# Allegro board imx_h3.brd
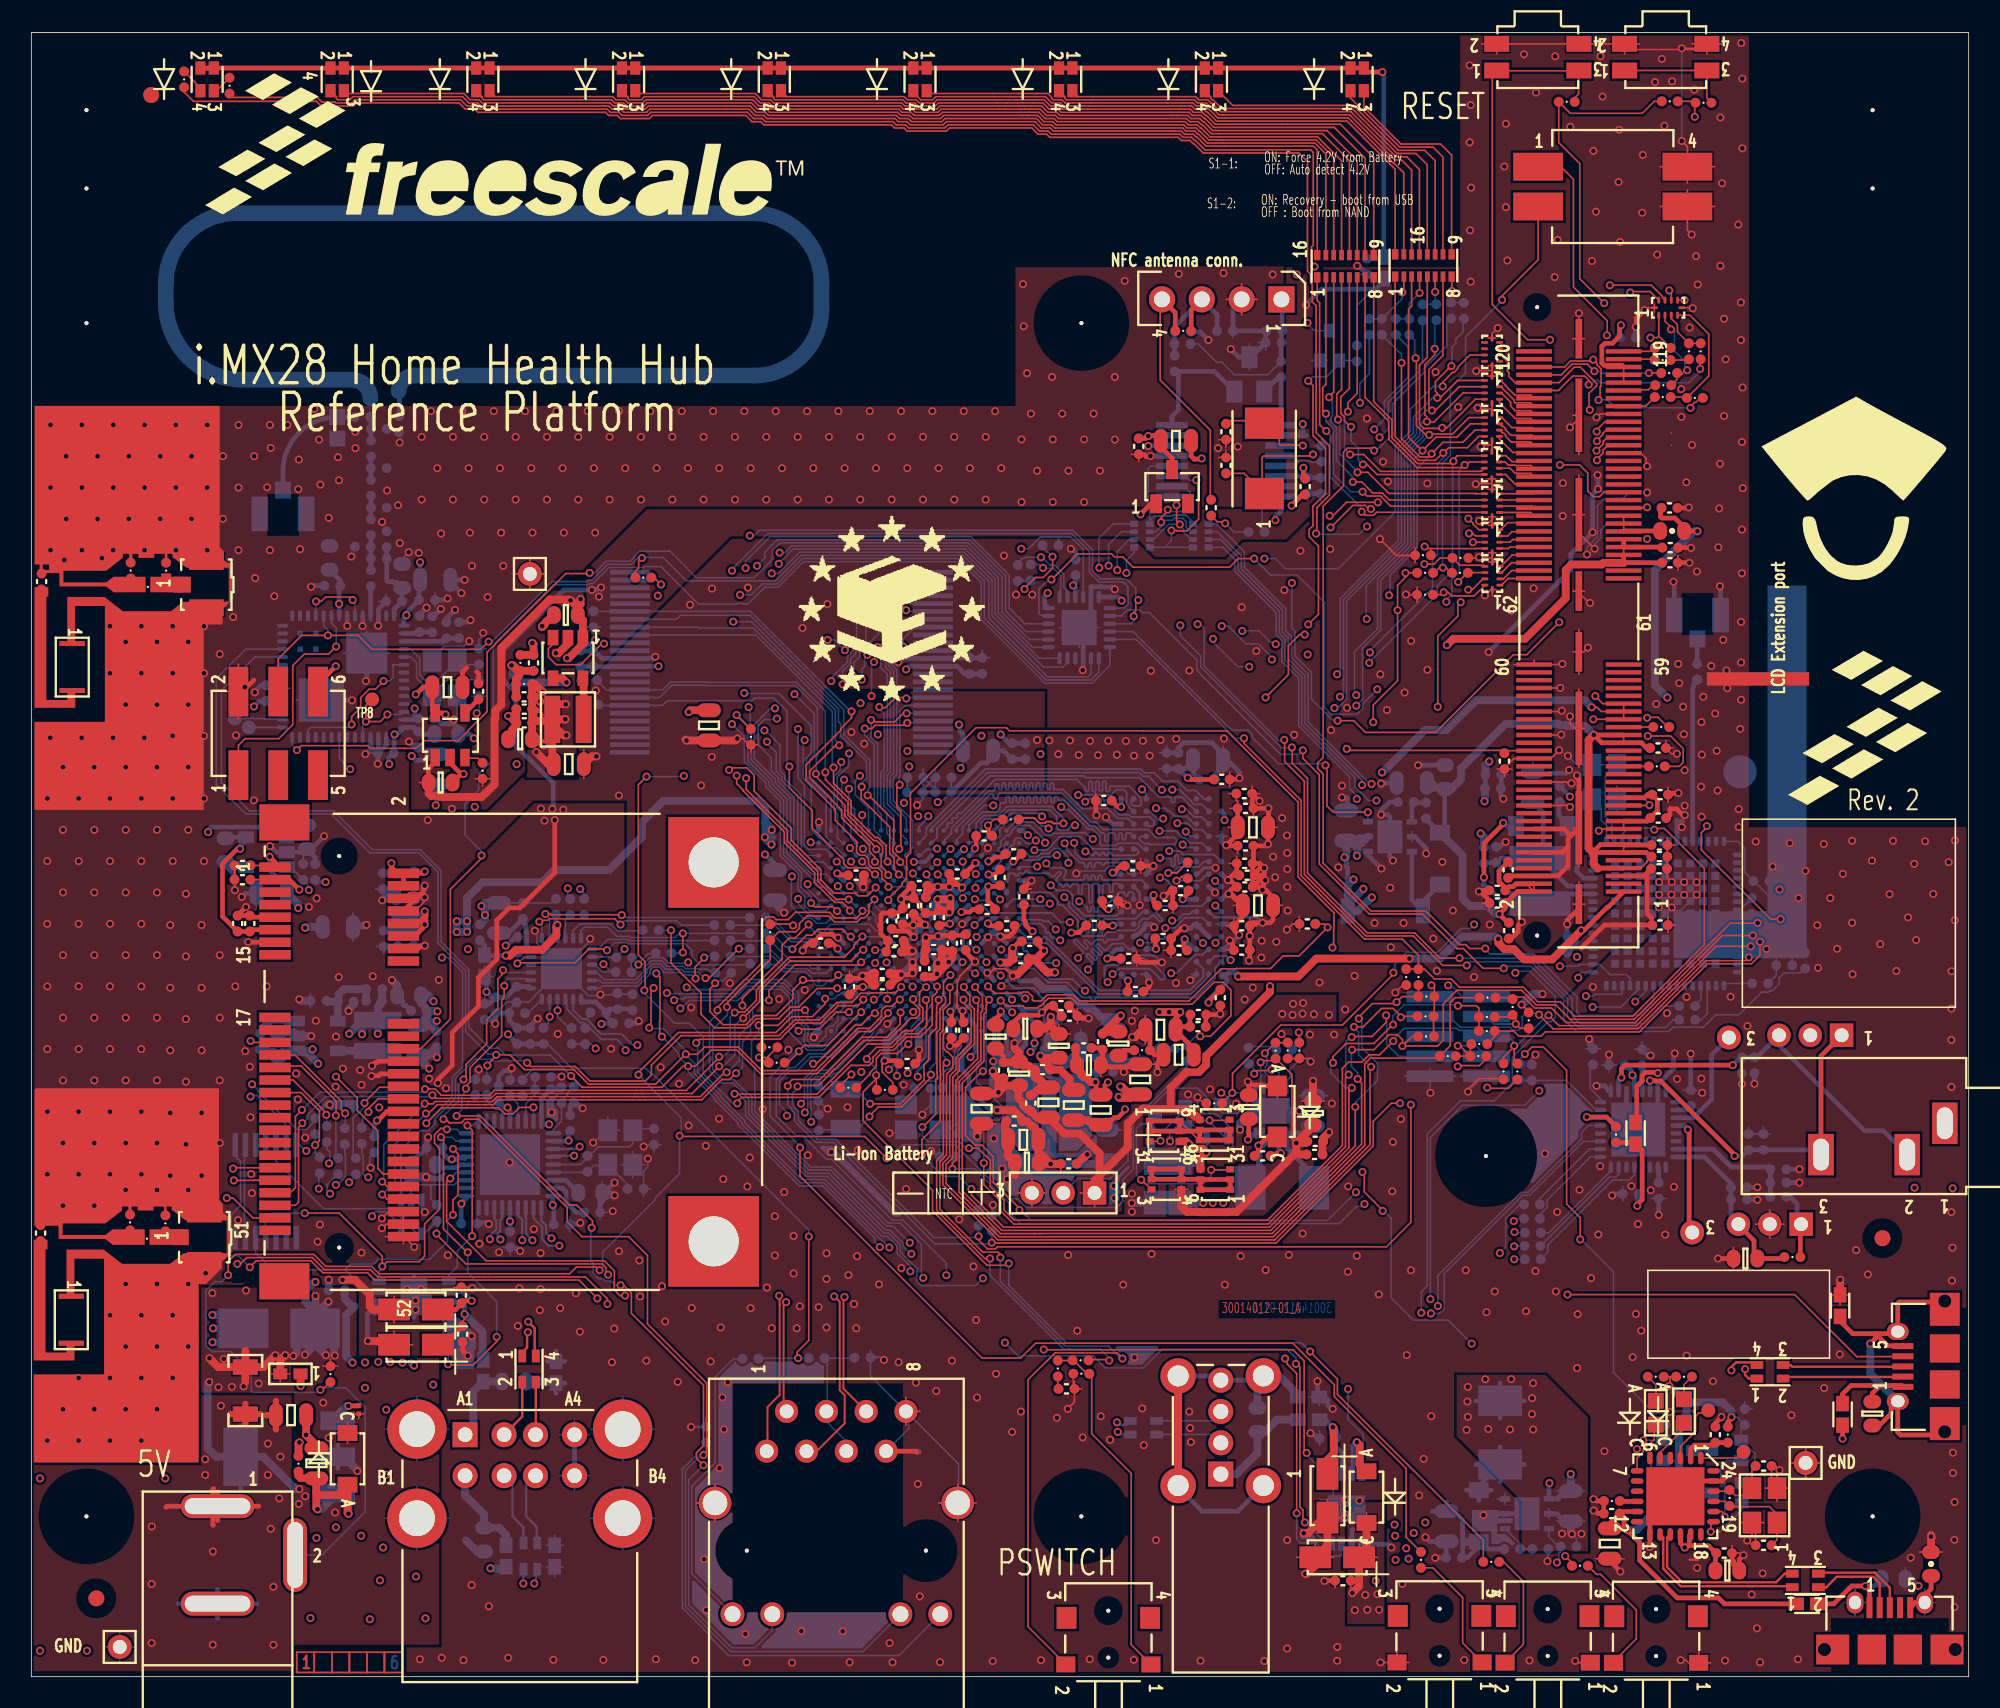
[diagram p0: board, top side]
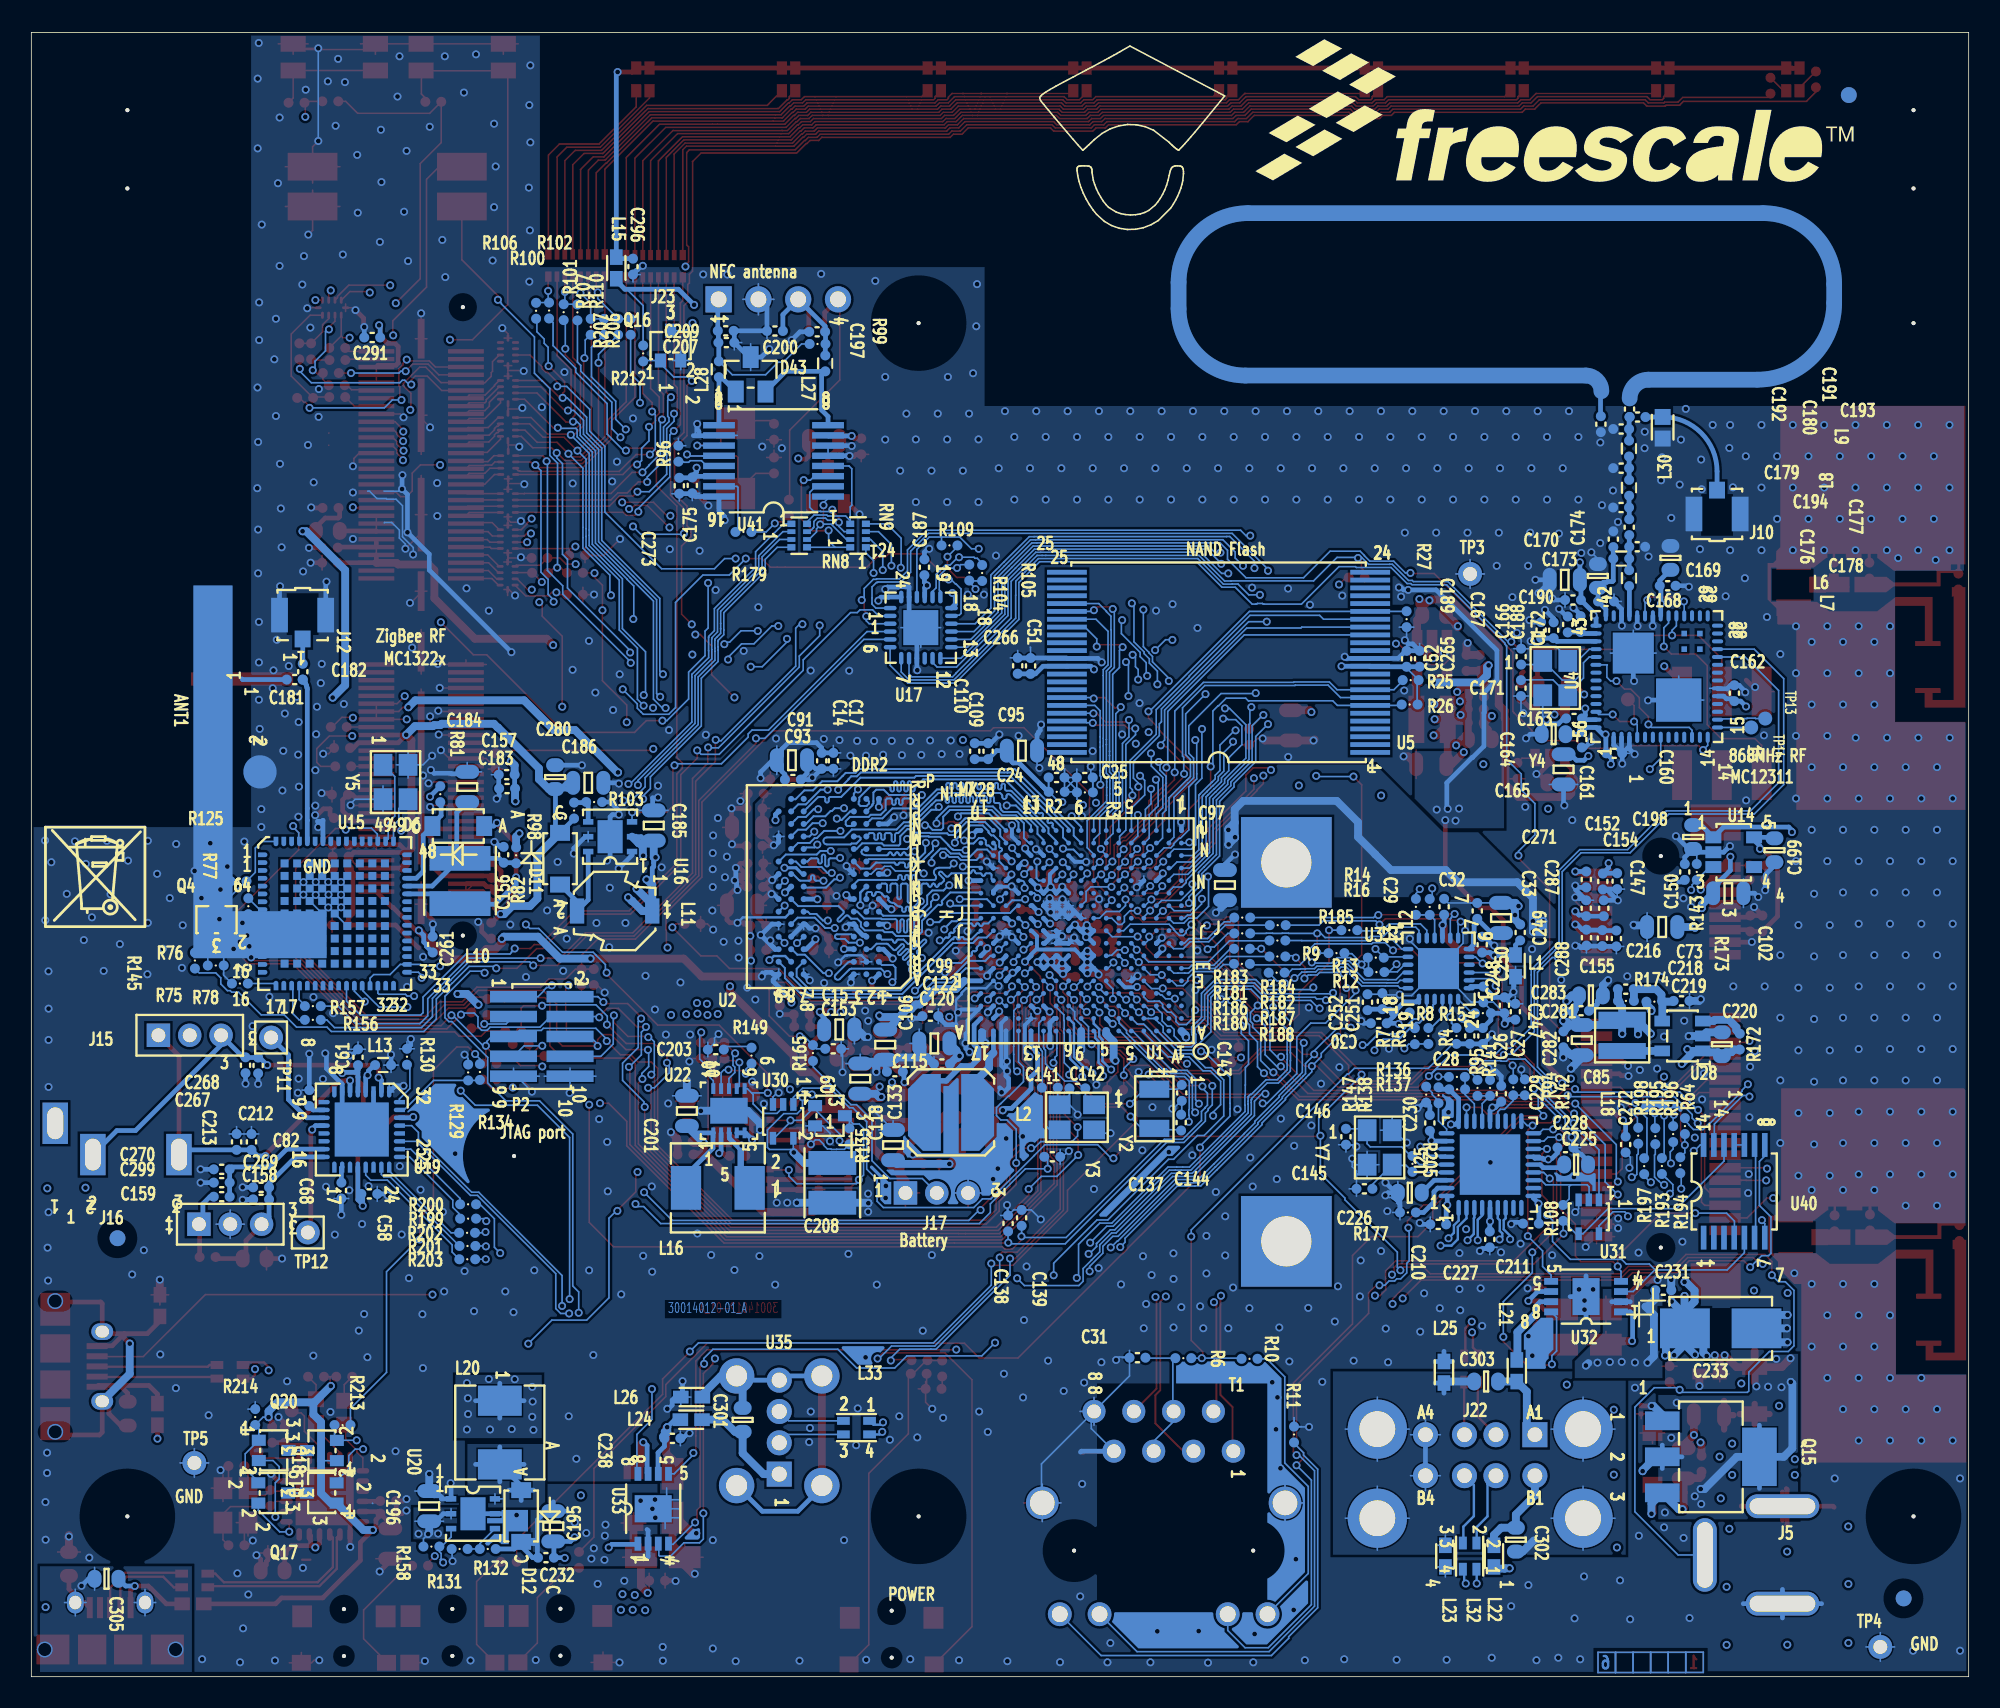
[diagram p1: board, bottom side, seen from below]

Outline 123.65 x 105 mm; copper layers: TOP, GND1, INT1, PWR, GND2, BOTTOM. Coordinates in mm from the lower left corner of the outline.
Outline path: 0,105 0,0 123.65,0 123.65,105 0,105

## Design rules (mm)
net group DDR2_CLK_DP: nets DDR2_CLK DDR2_CLK_B
net group DDR2_DQS0_DP: nets DDR2_DQS0 DDR2_DQS0_B
net group DDR2_DQS1_DP: nets DDR2_DQS1 DDR2_DQS1_B
net group ETH_RX_DIFF_PAIR: nets ETH_RXN ETH_RXP
net group ETH_TX_DIFF_PAIR: nets ETH_TXN ETH_TXP
net group USB0_DIFF_PAIR: nets USB0_DM USB0_DP
net group USB1_DIFF_PAIR: nets USB1_DM USB1_DP
net group USB_BOT_DIFF_PAIR: nets USB_BOT_DM USB_BOT_DP
net group USB_DEBUG_DIFF_PAIR: nets USB_DEBUG_DM USB_DEBUG_DP
net group USB_MODEM_DIFF_PAIR: nets USB_MODEM_DM USB_MODEM_DP
net group USB_TOP_DIFF_PAIR: nets USB_TOP_DM USB_TOP_DP
nets with their own width: min track width 0.12; nets DDR2_A0 DDR2_A1 DDR2_A2 DDR2_A3 DDR2_A4 DDR2_A5 DDR2_A6 DDR2_A7 DDR2_A8 DDR2_A9 DDR2_A10 DDR2_A11 DDR2_A12 DDR2_A13 DDR2_A14 DDR2_BA0 DDR2_BA1 DDR2_BA2 DDR2_CAS_B DDR2_CKE DDR2_CS_B DDR2_D00 DDR2_D01 DDR2_D02 DDR2_D03 DDR2_D04 DDR2_D05 DDR2_D06 DDR2_D07 DDR2_D08 DDR2_D09 DDR2_D10 DDR2_D11 DDR2_D12 DDR2_D13 DDR2_D14 DDR2_D15 DDR2_DQM0 DDR2_DQM1 DDR2_ODT0 DDR2_OPEN DDR2_RAS_B DDR2_WE_B

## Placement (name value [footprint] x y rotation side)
ANT1  F_Antenna  [F_ANTENNA_DIG528-2]  110.2 63.72 270 top
C1  10UF  [CC0805_OV]  78.29 49.25 0 top
C2  0.1UF  [CC0402_25]  77.26 47.95 0 top
C3  0.1UF  [CC0402_25]  77.26 46.4 0 top
C4  0.1UF  [CC0402_25]  75.89 43.36 270 top
C5  0.1UF  [CC0402_25]  74.45 41.5 0 top
C6  0.1UF  [CC0402_25]  68.45 55.95 180 top
C7  0.22uF  [CC0402_25]  70.47 43.75 0 top
C8  0.22uF  [CC0402_25]  77.5 55.45 0 top
C9  0.1UF  [CC0402_25]  77.5 53.06 0 top
C10  0.1UF  [CC0402_25]  68.85 49.53 0 top
C11  0.1UF  [CC0402_25]  77.45 50.43 0 top
C12  0.1UF  [CC0402_25]  77.6 51.18 0 top
C13  0.1UF  [CC0402_25]  70.03 45.86 0 top
C14  0.22uF  [CC0402_25]  73.2 58.49 90 bottom
C15  10UF  [CC0805_OV]  72.09 41.33 180 bottom
C16  0.01uF  [CC0402_25]  77.44 51.94 0 top
C17  0.01uF  [CC0402_25]  72.46 58.49 90 bottom
C18  0.1UF  [CC0402_25]  73.35 50.2 180 top
C19  0.1UF  [CC0402_25]  72.24 47.14 0 top
C20  0.1UF  [CC0402_25]  67.84 47.97 180 top
C21  0.1UF  [CC0402_25]  72.37 49.25 0 top
C22  0.1UF  [CC0402_25]  70.29 51.78 0 top
C23  0.22uF  [CC0402_25]  73.25 46.38 180 top
C24  0.1UF  [CC0402_25]  58.21 57.42 180 bottom
C25  0.1UF  [CC0402_25]  56.41 57.42 180 bottom
C26  0.01uF  [CC0402_25]  31.01 40.91 90 bottom
C27  0.01uF  [CC0402_25]  29.63 42.88 270 bottom
C28  0.1UF  [CC0402_25]  31.84 40.92 90 bottom
C29  0.01uF  [CC0402_25]  33.48 49.16 90 bottom
C30  0.01uF  [CC0402_25]  37.65 41.72 0 bottom
C31  0.022UF  [CC0402_25]  53.05 20.37 0 bottom
C32  0.1UF  [CC0402_25]  31.37 48.9 90 bottom
C33  10UF  [CC0805_OV]  29.84 48.45 90 bottom
C34  0.1UF  [CC0402_25]  107.48 15.46 90 top
C35  0.1UF  [CC0402_25]  100.87 10.41 180 top
C51  0.1UF  [CC0402_25]  59.88 64.54 90 bottom
C52  0.1UF  [CC0402_25]  35.88 65 90 bottom
C57  0.22uF  [CC0402_25]  57.59 46.43 180 top
C58  0.1UF  [CC0402_25]  102.08 30.83 180 bottom
C59  0.22uF  [CC0402_25]  57.02 45.21 90 top
C60  0.1UF  [CC0402_25]  57.95 48.47 90 top
C61  0.1UF  [CC0402_25]  102.8 39.56 90 bottom
C62  0.1UF  [CC0402_25]  58.78 46.84 90 top
C63  10UF  [CC0805_OV]  68.25 36.19 270 top
C64  0.22uF  [CC0402_25]  54.92 48.26 90 top
C65  0.1UF  [CC0402_25]  55.61 48.56 90 top
C66  0.1UF  [CC0402_25]  52.22 44.07 90 top
C67  0.1UF  [CC0402_25]  50.38 46.84 180 top
C68  0.1UF  [CC0402_25]  103.86 31.04 270 bottom
C69  0.1UF  [CC0402_25]  65.72 42.85 0 top
C70  0.1UF  [CC0402_25]  55.89 39.15 0 top
C71  0.1UF  [CC0402_25]  52.64 51.18 0 top
C72  0.1UF  [CC0402_25]  56.3 49.22 90 top
C73  10UF  [CC0805_OV]  19.56 47.88 0 bottom
C74  0.1UF  [CC0402_25]  54.31 44.91 180 top
C75  0.1UF  [CC0402_25]  54.31 44.19 180 top
C76  0.1UF  [CC0402_25]  55.06 46.29 180 top
C77  0.1UF  [CC0402_25]  55.17 47 180 top
C78  10UF  [CC0805_OV]  77.97 54.24 0 top
C79  0.1UF  [CC0402_25]  63.15 45.85 0 top
C80  0.1UF  [CC0402_25]  61 49 0 top
C81  0.22uF  [CC0402_25]  56.67 50.51 180 top
C82  0.1UF  [CC0402_25]  105.91 36.95 90 bottom
C83  0.1UF  [CC0402_25]  59.64 46.91 90 top
C84  0.22uF  [CC0402_25]  59.09 51.26 0 top
C85  10UF  [CC0805_OV]  24.7 40.65 270 bottom
C86  0.1UF  [CC0402_25]  59.5 41.28 270 top
C87  0.1UF  [CC0402_25]  60.81 53.69 0 top
C88  0.1UF  [CC0402_25]  62.7 52.54 0 top
C89  0.1UF  [CC0402_25]  63.72 46.96 0 top
C90  0.1UF  [CC0402_25]  57.09 49.26 270 top
C91  10UF  [CC0805_OV]  75.11 58.53 0 bottom
C92  0.1UF  [CC0402_25]  74.48 42.28 0 top
C93  0.1UF  [CC0402_25]  75.05 57.29 0 bottom
C94  0.1UF  [CC0402_25]  62.25 47.95 0 top
C95  10UF  [CC0805_OV]  60.42 59.13 180 bottom
C96  0.1UF  [CC0402_25]  63.35 49.8 270 top
C97  10UF  [CC0805_OV]  47.47 50.55 270 bottom
C98  0.1UF  [CC0402_25]  61.83 51.04 270 top
C99  0.01uF  [CC0402_25]  66.27 42.18 0 bottom
C100  0.1UF  [CC0402_25]  66.26 42.19 0 top
C101  1uF  [CC0603_OV]  63.44 41.38 0 top
C102  10UF  [CC0805_OV]  15.34 50.03 180 bottom
C103  22UF  [CC0805_OV]  43.25 60.75 270 top
C104  1uF  [CC0603_OV]  69.39 40.43 270 top
C105  0.1UF  [CC0402_25]  68.38 40.55 270 top
C106  10UF  [CC0805_OV]  69.15 40.36 270 bottom
C107  10UF  [CC0805_OV]  16.57 16.7 0 top
C108  0.1UF  [CC0402_25]  66.06 18.38 180 top
C109  0.01uF  [CC0402_25]  62.59 59.1 90 bottom
C110  0.1UF  [CC0402_25]  63.44 59.1 90 bottom
C111  1uF  [CC0603_OV]  61.55 40.87 270 top
C112  10UF  [CC0805_OV]  73.23 39.72 180 top
C113  22UF  [CC0805_OV]  72.06 41.31 180 top
C114  0.01uF  [CC0402_25]  67.16 40.16 0 top
C115  0.1UF  [CC0402_25]  68.53 38.63 0 bottom
C116  1uF  [CC0603_OV]  67.5 39.06 0 top
C117  10UF  [CC0805_OV]  70.77 38.14 90 top
C118  22UF  [CC0805_OV]  70.75 38.19 90 bottom
C119  0.01uF  [CC0402_25]  64.53 38.76 180 top
C120  0.1UF  [CC0402_25]  65.53 39.12 0 bottom
C121  1uF  [CC0603_OV]  65.59 40.28 90 top
C122  10UF  [CC0805_OV]  66.02 40.44 0 bottom
C123  22UF  [CC0805_OV]  66.53 36.5 270 top
C124  0.01uF  [CC0402_25]  63.78 36.62 90 top
C125  0.1UF  [CC0402_25]  62.05 38.72 90 top
C126  1uF  [CC0603_OV]  63.05 38.51 90 top
C127  10UF  [CC0805_OV]  64.91 36.67 90 top
C128  22UF  [CC0805_OV]  60.65 36.28 270 top
C129  0.01uF  [CC0402_25]  66.22 32.75 0 top
C130  0.1UF  [CC0402_25]  62.73 35.48 180 top
C131  1uF  [CC0603_OV]  63.54 32.83 180 top
C132  10UF  [CC0805_OV]  63.31 34.28 180 top
C133  22UF  [CC0805_OV]  68.65 33.95 90 bottom
C134  10UF  [CC0805_OV]  100.74 8.5 270 top
C135  0.1UF  [CC0402_25]  94.02 58.47 270 top
C136  0.1UF  [CC0402_25]  81.44 48.07 180 top
C137  0.1UF  [CC0402_25]  58.49 33.2 180 bottom
C138  0.1UF  [CC0402_25]  60.45 29.3 90 bottom
C139  0.1UF  [CC0402_25]  61.31 28.94 90 bottom
C140  0.1UF  [CC0402_25]  58.73 41.29 270 top
C141  10PF  [CC0402_25]  58.64 37.62 180 bottom
C142  10PF  [CC0402_25]  56.88 37.57 180 bottom
C143  12PF  [CC0402_25]  50.23 37.28 270 bottom
C144  12PF  [CC0402_25]  50.27 35.38 90 bottom
C145  10PF  [CC0402_25]  38.56 31.16 0 bottom
C146  10PF  [CC0402_25]  39.74 34.48 90 bottom
C147  0.1UF  [CC0402_25]  23.29 49.07 90 bottom
C148  12PF  [CC0402_25]  110.56 13.46 0 top
C149  12PF  [CC0402_25]  110.56 8.39 180 top
C150  0.1UF  [CC0402_25]  18.12 51.39 90 bottom
C151  0.1UF  [CC0402_25]  13.17 48.09 90 top
C152  0.1UF  [CC0402_25]  23.35 50.78 270 bottom
C153  0.1UF  [CC0402_25]  72.47 40.09 180 bottom
C154  0.1UF  [CC0402_25]  22.44 50.8 270 bottom
C155  0.1UF  [CC0402_25]  23.38 47.16 270 bottom
C156  10PF  [CC0402_25]  93.51 52.49 90 bottom
C157  10PF  [CC0402_25]  93.31 57.6 0 bottom
C158  10PF  [CC0402_25]  108.98 30.48 0 bottom
C159  10PF  [CC0402_25]  111.5 32.4 0 bottom
C160  0.1UF  [CC0402_25]  22.62 58.97 180 bottom
C161  0.1UF  [CC0402_25]  24.69 59.84 270 bottom
C162  0.1UF  [CC0402_25]  14.96 62.81 90 bottom
C163  0.1UF  [CC0402_25]  25.19 61.19 0 bottom
C164  1uF  [CC0603_OV]  26.49 60.19 0 bottom
C165  10UF  [CC0805_OV]  25.86 57.94 270 bottom
C166  0.1UF  [CC0402_25]  25.59 67.19 270 bottom
C167  0.1UF  [CC0402_25]  26.49 66.82 90 bottom
C168  0.1UF  [CC0402_25]  19.21 69.66 180 bottom
C169  1uF  [CC0603_OV]  19.04 71.44 90 bottom
C170  10UF  [CC0805_OV]  25.78 70.04 0 bottom
C171  9PF  [CC0402_25]  28.56 65.14 90 bottom
C172  9PF  [CC0402_25]  28.58 63.13 90 bottom
C173  0.1UF  [CC0402_25]  23.14 68.66 180 bottom
C174  1uF  [CC0603_OV]  23.66 70.29 90 bottom
C175  0.1UF  [CC0402_25]  81.47 76.07 270 bottom
C176  68PF  [CC0402_25]  22.68 72.64 90 bottom
C177  47PF  [CC0402_25]  21.66 73.41 90 bottom
C178  5.6PF  [CC0402_25]  21.16 72.16 180 bottom
C179  8.2PF  [CC0402_25]  22.18 77.18 0 bottom
C180  6.8PF  [CC0402_25]  22.18 79.67 0 bottom
C181  10PF  [CC0402_25]  106.84 63.68 0 bottom
C182  10PF  [CC0402_25]  106.33 64.18 90 bottom
C183  0.1UF  [CC0402_25]  93.29 56.72 0 bottom
C184  10UF  [CC0805_OV]  95.83 56.81 90 bottom
C185  10UF  [CC0805_OV]  83.93 54.35 90 bottom
C186  10UF  [CC0805_OV]  88.11 57.08 180 bottom
C187  0.1UF  [CC0402_25]  66.65 70.84 90 bottom
C188  100PF  [CC0402_25]  24.77 67.22 90 bottom
C189  100PF  [CC0402_25]  27.29 66.84 90 bottom
C190  100PF  [CC0402_25]  25.26 68.75 0 bottom
C191  6.8PF  [CC0402_25]  21.64 80.95 270 bottom
C192  6.8PF  [CC0402_25]  23.48 79.98 270 bottom
C193  6.8PF  [CC0402_25]  21.13 80.44 180 bottom
C194  8.2PF  [CC0402_25]  22.19 74.66 0 bottom
C195  10UF  [CC0805_OV]  90.34 9.6 270 bottom
C196  10UF  [CC0805_OV]  98.26 10.89 90 bottom
C197  68PF  [CC0402_25]  73.5 85.88 180 bottom
C198  1uF  [CC0603_OV]  17.59 53.62 270 bottom
C199  1uF  [CC0603_OV]  12.39 52.78 270 bottom
C200  68PF  [CC0402_25]  76.19 85.94 180 bottom
C201  22UF  [CC0805_OV]  81.81 36.13 90 bottom
C202  4.7UF  [CC0603_OV]  77.71 36.38 90 top
C203  680pF  [CC0402_25]  79.97 40.04 0 bottom
C204  0.47UF  [CC0402_25]  78.59 33.26 180 top
C205  4.7UF  [CC0603_OV]  108.25 6.78 0 top
C206  0.47UF  [CC0402_25]  108.05 7.9 0 top
C207  68PF  [CC0402_25]  79.29 85.19 180 bottom
C208  220UF  [CASE_B]  72.53 31.53 270 bottom
C209  68PF  [CC0402_25]  79.33 85.94 180 bottom
C210  0.1UF  [CC0402_25]  33.85 28.88 0 bottom
C211  0.1UF  [CC0402_25]  27.94 28.94 0 bottom
C212  10PF  [CC0402_25]  109.18 39.03 270 bottom
C213  10PF  [CC0402_25]  110.55 34.15 90 bottom
C214  10PF  [CC0402_25]  13.94 48.09 90 top
C215  10PF  [CC0402_25]  13.48 50.9 180 top
C216  10PF  [CC0402_25]  22.48 47.14 270 bottom
C217  10PF  [CC0402_25]  13.48 51.81 180 top
C218  6.8PF  [CC0402_25]  21.88 43.91 0 bottom
C219  33pF  [CC0402_25]  18.32 43.16 0 bottom
C220  4.7UF  [CC0603_OV]  15.75 40.38 90 bottom
C221  10UF  [CC0805_OV]  34.3 58.28 0 top
C222  4.7UF  [CC0603_OV]  34.12 67.8 180 top
C223  6.8PF  [CC0402_25]  31.45 62.57 0 top
C224  33pF  [CC0402_25]  32.05 64.74 270 top
C225  4.7UF  [CC0603_OV]  25.05 32.71 180 bottom
C226  4.7UF  [CC0603_OV]  35.67 30.91 0 bottom
C227  0.1UF  [CC0402_25]  30.56 27.93 270 bottom
C228  0.1UF  [CC0402_25]  25.73 33.78 180 bottom
C229  0.1UF  [CC0402_25]  29.84 37.22 90 bottom
C230  0.1UF  [CC0402_25]  34.39 35.36 90 bottom
C231  0.1UF  [CC0402_25]  19.49 24.68 180 bottom
C232  0.1UF  [CC0402_25]  90.81 7.6 180 bottom
C233  220uF  [CC6032]  15.82 22.25 180 bottom
C234  33uF  [CC3216]  24.55 21.2 180 top
C235  33uF  [CC3216]  24.55 23.45 180 top
C236  33uF  [CC3216]  83.34 7.62 180 top
C237  33uF  [CC3216]  82.73 11.56 270 top
C238  0.1UF  [CC0402_25]  82.73 15.22 180 bottom
C239  0.1UF  [CC0402_25]  27.45 24.35 90 top
C240  0.1UF  [CC0402_25]  27.52 21.87 270 top
C241  0.1UF  [CC0402_25]  83.71 6.13 180 top
C242  330pF  [CC0402_25]  75.3 74.65 90 top
C243  18PF  [CC0402_25]  76.25 77.35 90 top
C244  18PF  [CC0402_25]  76.25 79.5 270 top
C245  0.01uF  [CC0402_25]  77.42 56.39 0 top
C246  180pF  [CC0402_25]  75.98 57.31 0 top
C247  47PF  [CC0402_25]  28.94 42.47 270 bottom
C248  47PF  [CC0402_25]  30.98 43.56 270 bottom
C249  47PF  [CC0402_25]  28.62 47.53 90 bottom
C250  10PF  [CC0402_25]  31.05 46.75 90 bottom
C251  10PF  [CC0402_25]  37.42 43.13 90 bottom
C252  10PF  [CC0402_25]  38.37 43.07 90 bottom
C253  0.1UF  [CC0402_25]  28.55 62.93 90 top
C254  47PF  [CC0402_25]  104.56 74.63 0 top
C255  47PF  [CC0402_25]  103.89 51.59 0 top
C256  47PF  [CC0402_25]  103.82 59.31 0 top
C257  47PF  [CC0402_25]  103.96 56.32 0 top
C258  47PF  [CC0402_25]  103.91 53.11 0 top
C259  47PF  [CC0402_25]  103.91 52.37 0 top
C260  47PF  [CC0402_25]  103.95 48 0 top
C261  47PF  [CC0402_25]  98.04 46.75 90 bottom
C262  47PF  [CC0402_25]  93.57 49.41 180 top
C263  47PF  [CC0402_25]  104.59 71.13 0 top
C264  47PF  [CC0402_25]  103.84 54.83 0 top
C265  47PF  [CC0402_25]  35.05 65 90 bottom
C266  47PF  [CC0402_25]  60.7 64.56 90 bottom
C267  47PF  [CC0402_25]  109.6 34.15 90 bottom
C268  47PF  [CC0402_25]  109.98 39.04 270 bottom
C269  47PF  [CC0402_25]  108.98 31.25 0 bottom
C270  47PF  [CC0402_25]  111.5 31.55 0 bottom
C271  10PF  [CC0402_25]  24.41 50.91 270 bottom
C272  10PF  [CC0402_25]  21.89 33.99 270 bottom
C273  10PF  [CC0402_25]  82.3 76.05 270 bottom
C274  47PF  [CC0402_25]  81.3 76 270 top
C275  0.1UF  [CC0402_25]  81.9 33.35 0 top
C276  0.01uF  [CC0402_25]  81.95 34.19 0 top
C277  1uF  [CC0603_OV]  81.8 36 90 top
C278  0.1UF  [CC0402_25]  93.57 50.22 180 top
C279  0.01uF  [CC0402_25]  94.26 51.52 270 top
C280  1uF  [CC0603_OV]  90.22 57.44 90 bottom
C281  0.1UF  [CC0402_25]  24.74 42.53 180 bottom
C282  0.01uF  [CC0402_25]  25.87 40.7 270 bottom
C283  1uF  [CC0603_OV]  24.11 43.5 180 bottom
C284  0.1UF  [CC0402_25]  31.46 60.91 180 top
C285  0.01uF  [CC0402_25]  31.46 61.78 180 top
C286  1uF  [CC0603_OV]  31.2 59.86 180 top
C287  10PF  [CC0402_25]  24.41 49.07 90 bottom
C288  10PF  [CC0402_25]  24.39 47.19 270 bottom
C289  47PF  [CC0402_25]  104.6 72.1 0 top
C290  47PF  [CC0402_25]  94.3 47.65 270 top
C291  47PF  [CC0402_25]  101.9 85.52 0 bottom
C292  1uF  [CC0603_OV]  26.12 57.1 0 top
C293  10UF  [CC0805_OV]  26.55 63.19 0 top
C294  0.1UF  [CC0402_25]  70.68 78.56 270 top
C295  10UF  [CC0805_OV]  18.19 13.62 90 top
C296  0.1UF  [CC0402_25]  85.25 90.05 270 bottom
C297  6.8PF  [CC0402_25]  0.66 69.94 90 top
C298  6.8PF  [CC0402_25]  0.59 28.33 90 top
C299  0.1UF  [CC0402_25]  111.5 30.65 180 bottom
C300  1uF  [CC0603_OV]  109.4 26.7 180 top
C301  1uF  [CC0603_OV]  78.25 16.4 90 bottom
C302  1uF  [CC0603_OV]  28.9 8.75 270 bottom
C303  1uF  [CC0603_OV]  30.8 18.85 0 bottom
C304  1uF  [CC0603_OV]  117.5 16.8 270 top
C305  1uF  [CC0603_OV]  118.85 6.25 0 bottom
D3  LED_RED-GRN  [LED_DUAL_0605_SM]  11.22 102 270 top
D4  MBR120LSFT1G  [SOD123]  85.22 11.47 90 top
D6  MBR0520LT1G  [SOD123]  96.4 54.32 180 bottom
D7  LED_GREEN  [LED_0603]  103.68 16.85 270 top
D8  LED_GREEN  [LED_0603]  105.48 16.96 270 top
D11  MBR120LSFT1G  [SOD123]  89.91 52.24 270 bottom
D12  MBR120LSFT1G  [SOD123]  92.39 10.26 90 bottom
D17  MBR120VLSFT1G  [SOD-123]  79.53 36.09 270 top
D35  LED_RED-GRN  [LED_DUAL_0605_SM]  56.72 102 270 top
D36  LED_RED-GRN  [LED_DUAL_0605_SM]  66.02 102 270 top
D37  LED_RED-GRN  [LED_DUAL_0605_SM]  75.32 102 270 top
D38  LED_RED-GRN  [LED_DUAL_0605_SM]  84.62 102 270 top
D39  LED_RED-GRN  [LED_DUAL_0605_SM]  19.52 102 270 top
D40  LED_RED-GRN  [LED_DUAL_0605_SM]  28.82 102 270 top
D41  LED_RED-GRN  [LED_DUAL_0605_SM]  38.12 102 270 top
D42  LED_RED-GRN  [LED_DUAL_0605_SM]  47.42 102 270 top
D43  BAT54C  [SOT-23]  77.74 83.17 180 bottom
D44  BZX84C11LT1G  [SOT23]  72.81 76 0 top
D45  MMSZ5231BT1G  [SOD123]  20.18 13.91 270 top
E5  ANTENNA_2.4GHZ  [ANTENNA_3316]  2.61 64.47 270 top
E6  ANTENNA_2.4GHZ  [ANTENNA_3316]  2.55 22.79 270 top
F1  1.5A  [FUSE_SMDC150F]  13.66 18.27 270 top
FL1  NFA18SL307  [FILTER_NFA18SD]  93.23 84.6 180 top
FL2  NFA18SL307  [FILTER_NFA18SD]  93.23 82.17 180 top
FL3  NFA18SL307  [FILTER_NFA18SD]  93.23 79.81 180 top
FL4  NFA18SL307  [FILTER_NFA18SD]  93.22 77.37 180 top
FL5  NFA18SL307  [FILTER_NFA18SD]  93.23 74.94 180 top
FL6  NFA18SL307  [FILTER_NFA18SD]  93.24 72.65 180 top
FL7  NFA18SL307  [FILTER_NFA18SD]  93.25 70.31 180 top
FL8  NFA18SL307  [FILTER_NFA18SD]  104.47 87.42 90 top
J5  DC_POWER_JACK  [CONN_DC_POWER_3P]  11.88 10.88 0 top
J7  MICRO USB AB 5  [CON5_MICROUSB]  122.12 19.81 90 top
J8  MICRO USB AB 5  [CON5_MICROUSB]  118.62 1.74 0 top
J9  U.FL  [CON_3_UFL_R_SMT]  11.04 28.06 90 top
J10  U.FL  [CON_3_UFL_R_SMT]  16.06 74.25 180 bottom
J11  HDR_2X3  [HDR203_TSM2_SM]  15.76 60.24 90 top
J12  U.FL  [CON_3_UFL_R_SMT]  106.34 67.79 0 bottom
J13  QSH-060-01-L-D-A  [CON_120S_QSH_SM_05PITCH]  98.77 67.38 90 top
J14  U.FL  [CON_3_UFL_R_SMT]  11.17 69.74 90 top
J15  HDR_1X3  [HDR103_78MIL]  115.54 40.96 0 bottom
J16  HDR_1X3  [HDR103_78MIL]  112.96 28.9 0 bottom
J17  HDR_1X3  [HDR103_78MIL]  67.86 30.89 0 top
J18  AUD 3  [CON_AUD_3_TH_RA]  122.12 35.34 180 top
J20  CON 2X26 MINI PCI EXPRESS  [CON_2X26_0P8_SMT_A]  19.65 39.9 90 top
J22  USB_TYPE_A_DUAL  [AMP-787745-X]  27.69 15.45 0 top
J23  HDR 1X4  [HDR104_929]  79.79 87.95 270 top
L1  470OHM  [IND_0603]  28.92 45.4 90 bottom
L2  15UH  [VLF5020]  64.95 36.03 0 bottom
L3  470OHM  [IND_0603]  115.6 16.75 90 top
L4  470OHM  [IND_0603]  115.45 23.69 90 top
L5  470OHM  [IND_0603]  113.34 4.65 0 top
L6  33nH  [IND_0402]  22.18 71.4 180 bottom
L7  4.7NH  [IND_0402]  21.67 70.15 90 bottom
L8  6.8NH  [IND_0402]  21.67 75.92 90 bottom
L9  6.8NH  [IND_0402]  21.68 78.43 90 bottom
L10  100UH  [IND_VLF4018]  96.29 50.81 90 bottom
L11  10UH  [IND_VLF5014A]  86.42 48.9 0 bottom
L12  470OHM  [IND_0603]  102.4 34.7 90 top
L13  75 OHM  [IND_0402]  101.2 39.06 180 bottom
L15  470OHM  [IND_0603]  86.32 89.96 270 bottom
L16  4.7UH  [IND_IHLP_2020]  79.84 31.22 0 bottom
L18  4.7UH  [IND_VLS3012_SM]  22.12 40.96 90 bottom
L19  4.7UH  [IND_VLS3012_SM]  34.25 61.13 180 top
L20  10uH  [IND_IHLP_2020]  93.75 15.59 270 bottom
L21  470 Ohm  [IND_0603]  28.84 19.53 270 bottom
L22  470 Ohm  [IND_0603]  30.3 7.7 90 bottom
L23  470 Ohm  [IND_0603]  33.4 7.7 90 bottom
L24  470 Ohm  [IND_0603]  81.54 16.41 180 bottom
L25  470 Ohm  [IND_0603]  33.49 19.44 270 bottom
L26  470 Ohm  [IND_0603]  81.51 17.85 180 bottom
L27  2.2uH  [IND_0402]  72.98 83.86 90 bottom
L28  2.2uH  [IND_0402]  79.77 83.49 90 bottom
L29  90 OHM@100MHZ  [IND_0805_4P]  110.97 19.47 180 top
L30  LQW18ANR27G00  [IND_0603A]  19.53 79.75 270 bottom
L31  90 OHM@100MHZ  [IND_0805_4P]  31.77 19.65 90 top
L32  90 OHM@100MHZ  [IND_0805_4P]  31.85 7.7 270 bottom
L33  90 OHM@100MHZ  [IND_0805_4P]  70.98 15.91 180 bottom
L34  90 OHM@100MHZ  [IND_0805_4P]  113.23 6.15 180 top
NOREF  -  []  250.5 -53.5 0 top
NOREF#2  -  []  3.52 10.24 90 top
NOREF#3  -  [unnamed#2]  4.15 5 0 top
NOREF#4  -  [unnamed#2]  7.65 101 0 top
NOREF#5  -  []  251.55 -65.5 0 top
NOREF#6  -  []  0.15 104.3 0 top
NOREF#7  -  []  -30.04 205.28 0 top
NOREF#8  -  [unnamed#2]  117.52 10.24 0 top
NOREF#9  -  []  3.52 95.03 90 top
NOREF#10  -  []  112.12 55.66 0 top
NOREF#11  -  []  3.52 100.03 90 top
NOREF#12  -  [unnamed#2]  118.15 28 0 top
NOREF#13  -  [unnamed#2]  117.52 100.03 0 top
NOREF#14  -  []  110.39 69.93 0 top
NOREF#15  -  []  3.52 86.44 0 top
NOREF#16  -  []  0 105 0 top
NOREF#17  -  [unnamed#2]  3.52 86.44 0 top
NOREF#18  -  [unnamed#2]  92.84 33.25 0 top
NOREF#19  -  []  0 102 0 top
NOREF#20  -  []  -75.6 -287.9 0 top
NOREF#21  -  [unnamed#2]  117.52 95.03 0 top
NOREF#22  -  []  35.69 79.34 0 top
NOREF#23  -  []  0 3.7 0 top
NOREF#24  -  []  3.52 86.44 90 top
NOREF#25  -  [unnamed#2]  67.02 10.24 0 top
NOREF#26  -  []  3.52 10.24 0 top
NOREF#27  -  []  3.52 100.03 0 top
NOREF#28  -  []  0.15 4.5 0 top
NOREF#29  -  [unnamed#2]  67.02 86.44 0 top
NOREF#30  -  [unnamed#2]  3.52 100.03 0 top
NOREF#31  -  []  3.52 10.24 0 top
NOREF#32  -  []  11.08 93.98 0 top
NOREF#33  -  []  0.15 0 90 top
NOREF#34  -  []  3.52 10.24 0 top
NOREF#35  -  []  3.15 0 90 top
NOREF#36  -  [unnamed#2]  3.52 95.03 0 top
NOREF#37  -  [unnamed#2]  3.52 10.24 0 top
NOREF#38  -  [unnamed#2]  118.15 28 180 bottom
NOREF#39  -  [unnamed#2]  4.15 5 180 bottom
NOREF#40  -  [unnamed#2]  7.65 101 180 bottom
NOREF#41  -  []  47.45 89.75 180 bottom
NOREF#42  -  []  122.75 47.9 180 bottom
P2  HDR 2X5  [CON_2X5_FTS_SM]  91.07 40.88 270 bottom
Q4  NTS4001NT1G  [SC70_3]  111.83 48.34 180 bottom
Q5  NTJS4151P  [SOT363]  72.45 31.76 270 top
Q6  NTJS4151P  [SOT363]  75.57 31.75 90 top
Q9  NTS4001NT1G  [SC70_3]  72.67 35.82 270 bottom
Q13  NTJS4151P  [SOT363]  72.34 34.84 270 top
Q14  NTJS4151P  [SOT363]  75.53 34.91 90 top
Q15  S602TSRP  [SOT223]  16.45 14.04 270 bottom
Q16  NTS4001NT1G  [SC70_3]  82.85 85 180 bottom
Q17  NTS4001NT1G  [SC70_3]  105.12 11.73 90 bottom
Q18  NTS4001NT1G  [SC70_3]  108.21 11.73 270 bottom
Q19  NTS4001NT1G  [SC70_3]  105.1 14.44 90 bottom
Q20  NTS4001NT1G  [SC70_3]  108.18 14.45 270 bottom
R1  100  [RC0402_25]  73.81 51.49 90 top
R2  1K  [RC0402_25]  58.2 56.5 180 bottom
R3  1K  [RC0402_25]  56.41 56.47 180 bottom
R4  49.9  [RC0402_25]  32.69 40.92 90 bottom
R5  49.9  [RC0402_25]  34.48 40.91 90 bottom
R6  0  [RC0402_25]  50.12 20.34 0 bottom
R7  49.9  [RC0402_25]  35.35 40.9 90 bottom
R8  49.9  [RC0402_25]  36.19 42.41 180 bottom
R9  4.7K  [RC0402_25]  40.35 46.21 0 bottom
R10  270  [RC0402_25]  45.9 20.3 0 bottom
R11  270  [RC0402_25]  43.06 15.47 90 bottom
R12  10.0K  [RC0402_25]  37.8 45 180 bottom
R13  10.0K  [RC0402_25]  37.84 45.91 0 bottom
R14  10.0K  [RC0402_25]  34.4 49.16 90 bottom
R15  12.1K  [RC0402_25]  31.01 42.37 180 bottom
R16  10.0K  [RC0402_25]  35.28 49.16 270 bottom
R17  10.0K  [RC0402_25]  47.16 47.54 270 top
R18  10.0K  [RC0402_25]  100.88 11.22 0 top
R19  10.0K  [RC0402_25]  108.28 15.46 270 top
R20  100  [RC0402_25]  17.05 13.6 90 top
R25  10.0K  [RC0402_25]  35.62 63.64 0 bottom
R26  10.0K  [RC0402_25]  35.68 62.08 0 bottom
R27  47K  [RC0402_25]  35.88 67.53 270 bottom
R39  1K  [RC0402_25]  66.97 20.21 180 top
R41  1K  [RC0402_25]  65.52 19.68 270 top
R42  1  [RC0402_25]  70.89 40 0 top
R43  100K  [RC0402_25]  67.02 19.34 180 top
R44  470K  [RC0402_25]  19.09 19.32 270 top
R45  10.0K  [RC0402_25]  98 100.57 180 top
R46  453  [RC0402_25]  9.75 102 90 top
R47  1.0M  [RC0402_25]  108.4 11.41 90 top
R49  10.0K  [RC0402_25]  52.14 37.61 180 top
R51  10.0K  [RC0402_25]  95.57 41.91 270 top
R52  10.0K  [RC0402_25]  94.84 38.65 90 top
R53  10.0K  [RC0402_25]  92.36 39.63 180 top
R54  10.0K  [RC0402_25]  89.04 43.43 180 top
R55  10.0K  [RC0402_25]  88.99 42.17 180 top
R56  10.0K  [RC0402_25]  89.02 40.88 180 top
R57  10.0K  [RC0402_25]  93.96 38.66 270 top
R58  10.0K  [RC0402_25]  62.51 54.74 180 top
R64  22K  [RC0402_25]  18.11 35.16 270 bottom
R66  10.0K  [RC0402_25]  39.06 70.19 0 top
R68  453  [RC0402_25]  103.68 19.16 180 top
R69  453  [RC0402_25]  105.48 19.16 0 top
R75  10.0K  [RC0402_25]  111.88 45.41 180 bottom
R76  10.0K  [RC0402_25]  111.88 46.25 180 bottom
R77  10.0K  [RC0402_25]  110.43 50.8 0 bottom
R78  0  [RC0402_25]  110.34 44.26 180 bottom
R80  10.0K  [RC0402_25]  87.75 44.68 270 top
R81  0  [RC0402_25]  97.55 56.35 270 bottom
R82  0  [RC0402_25]  92.71 52.45 270 bottom
R83  0  [RC0402_25]  104.12 81.72 0 top
R84  0  [RC0402_25]  106.18 81.66 180 top
R85  0  [RC0402_25]  104.12 84.08 0 top
R86  0  [RC0402_25]  104.12 84.85 0 top
R87  0  [RC0402_25]  104.03 60.65 0 top
R88  0  [RC0402_25]  104.16 82.47 0 top
R89  0  [RC0402_25]  104.54 83.25 0 top
R90  0  [RC0402_25]  105.8 84.64 90 top
R91  0  [RC0402_25]  106.55 84.64 90 top
R92  0  [RC0402_25]  103.75 58.13 0 top
R93  0  [RC0603_OV]  104.73 73.16 0 top
R94  0  [RC0402_25]  29.06 37.63 90 bottom
R95  0  [RC0402_25]  31.35 37.6 90 bottom
R96  0  [RC0402_25]  82.35 78.1 90 bottom
R97  0  [RC0402_25]  73.52 85.94 180 top
R98  30.1K  [RC0402_25]  89.01 55.31 90 bottom
R99  0  [RC0402_25]  73.47 85.11 180 bottom
R100  0  [RC0402_25]  89.68 87.14 90 bottom
R101  0  [RC0402_25]  88.8 87.12 90 bottom
R102  0  [RC0402_25]  90.61 87.24 90 bottom
R103  10.0K  [RC0402_25]  87.73 55.85 180 bottom
R104  4.7K  [RC0402_25]  63.78 70.5 90 bottom
R105  4.7K  [RC0402_25]  62.96 70.48 90 bottom
R106  0  [RC0402_25]  91.44 87.22 90 bottom
R107  0  [RC0402_25]  87.95 86.2 90 bottom
R108  0  [RC0402_25]  25.88 29.62 270 bottom
R109  10.0K  [RC0402_25]  65.05 72.24 0 bottom
R110  0  [RC0402_25]  87.1 86.2 90 bottom
R118  4.7K  [RC0402_25]  88.96 70.49 0 top
R119  47K  [RC0402_25]  88.96 69.09 180 top
R120  47K  [RC0402_25]  45.92 60.01 270 top
R121  47K  [RC0402_25]  91.18 70.49 180 top
R122  47K  [RC0402_25]  91.22 71.44 0 top
R123  47K  [RC0402_25]  88.82 71.62 180 top
R124  47K  [RC0402_25]  47.57 39.21 180 top
R125  0  [RC0402_25]  109.8 49.2 270 bottom
R126  47K  [RC0402_25]  54.48 37.47 0 top
R127  4.7K  [RC0402_25]  106.73 100.51 0 top
R128  0  [RC0402_25]  101.14 34.62 90 top
R129  0  [RC0402_25]  95.77 38.59 90 bottom
R130  0  [RC0402_25]  99.68 39.59 90 bottom
R131  10.0K  [RC0402_25]  96.32 8.16 0 bottom
R132  30.1K  [RC0402_25]  94.52 8.16 0 bottom
R134  10.0K  [RC0402_25]  95.02 38.62 90 bottom
R135  10.0K  [RC0402_25]  71.44 34.5 90 bottom
R136  10.0K  [RC0402_25]  32.66 38.3 0 bottom
R137  10.0K  [RC0402_25]  32.65 37.51 180 bottom
R138  10.0K  [RC0402_25]  33.84 37.13 270 bottom
R140  47K  [RC0402_25]  47.11 40.19 0 top
R141  10.0K  [RC0402_25]  30.55 37.6 90 bottom
R142  10.0K  [RC0402_25]  28.33 37.63 90 bottom
R143  10.0K  [RC0402_25]  17.36 51.39 90 bottom
R144  4.7K  [RC0402_25]  88.7 7.46 270 top
R145  0  [RC0402_25]  113.21 45.73 90 bottom
R146  0  [RC0402_25]  88.54 44.68 90 top
R147  10.0K  [RC0402_25]  34.62 37.17 270 bottom
R148  200K  [RC0402_25]  80.19 39.99 270 top
R149  16.2K  [RC0402_25]  77.69 39.66 270 bottom
R150  60.4K  [RC0402_25]  80.93 39.99 270 top
R151  47K  [RC0402_25]  104.57 100.6 180 top
R152  4.7K  [RC0402_25]  93.18 7.34 180 top
R153  4.7K  [RC0402_25]  98.84 7.09 180 top
R155  10.0K  [RC0402_25]  75.5 36.62 0 top
R156  0  [RC0402_25]  105.69 41.94 180 bottom
R157  0  [RC0402_25]  105.69 42.82 180 bottom
R158  10.0K  [RC0402_25]  98.12 8.31 180 bottom
R159  0  [RC0402_25]  92.9 42.13 0 top
R160  0  [RC0402_25]  92.94 43.36 180 top
R161  0  [RC0402_25]  92.42 40.4 0 top
R162  0  [RC0402_25]  94.55 42.76 270 top
R163  0  [RC0402_25]  90.41 39.63 180 top
R164  0  [RC0402_25]  92.9 41.23 0 top
R165  0  [RC0402_25]  73.77 39.82 90 bottom
R166  0  [RC0402_25]  7.38 27.97 0 top
R167  0  [RC0402_25]  7.44 69.59 0 top
R168  0  [RC0402_25]  8.56 28.95 90 top
R169  0  [RC0402_25]  6.3 29 90 top
R170  0  [RC0402_25]  8.6 70.63 90 top
R171  0  [RC0402_25]  6.34 70.63 270 top
R172  10.0K  [RC0402_25]  14.61 40.56 90 bottom
R173  0  [RC0402_25]  20.06 43.1 0 bottom
R174  0  [RC0402_25]  21.88 43.16 180 bottom
R175  0  [RC0402_25]  31.22 64.74 90 top
R176  464K  [RC0402_25]  79.41 39.97 270 top
R177  12.0K  [RC0402_25]  35.79 29.65 0 bottom
R178  0  [RC0402_25]  31.45 63.39 180 top
R179  220K  [RC0402_25]  78.2 73.1 180 bottom
R180  10  [RC0402_25]  46.38 45.52 180 bottom
R181  10  [RC0402_25]  46.37 47.47 180 bottom
R182  10  [RC0402_25]  44.12 47.01 180 bottom
R183  10  [RC0402_25]  46.37 48.47 180 bottom
R184  10  [RC0402_25]  44.1 47.99 180 bottom
R185  10  [RC0402_25]  39.53 47.67 180 bottom
R186  10  [RC0402_25]  46.38 46.49 180 bottom
R187  10  [RC0402_25]  44.12 45.99 180 bottom
R188  10  [RC0402_25]  44.17 44.96 180 bottom
R193  10  [RC0402_25]  19.58 32.61 90 bottom
R194  10  [RC0402_25]  18.41 32.66 90 bottom
R195  10  [RC0402_25]  20 34.51 90 bottom
R196  10  [RC0402_25]  18.86 34.65 90 bottom
R197  10  [RC0402_25]  20.71 32.6 90 bottom
R198  10  [RC0402_25]  21.09 34.54 90 bottom
R199  10  [RC0402_25]  95.78 29.25 0 bottom
R200  10  [RC0402_25]  95.78 30.16 0 bottom
R201  10  [RC0402_25]  95.82 27.5 0 bottom
R202  10  [RC0402_25]  95.84 28.34 0 bottom
R203  10  [RC0402_25]  95.83 26.66 0 bottom
R204  0  [RC0805_OV]  73.06 78.92 0 top
R205  1.0M  [RC0402_25]  35.5 32.75 270 bottom
R206  0  [RC0402_25]  85.4 86.2 90 bottom
R207  0  [RC0402_25]  86.2 86.2 90 bottom
R208  0  [RC0603_OV]  121.25 7.2 270 top
R209  0  [RC0402_25]  112.4 26.8 0 top
R210  10.0K  [RC0402_25]  28.8 57.85 90 top
R211  453  [RC0402_25]  12.65 101.6 270 top
R212  10.0K  [RC0402_25]  84.6 84.5 270 bottom
R213  10.0K  [RC0402_25]  103.79 16.07 180 bottom
R214  1.0M  [RC0402_25]  109.36 16.58 270 bottom
RN6  470  [RCA8_16]  88.85 90.11 90 top
RN7  470  [RCA8_16]  83.88 90.07 90 top
RN8  0  [CRN_8_0P5_2X1]  74.64 72.87 180 bottom
RN9  0  [CRN_8_0P5_2X1]  70.89 72.87 0 bottom
S1  SW_DIP-2/SM  [DIP-SMT2]  100.94 95.16 0 top
SW2  ATCA Handle Switch  [SW2_SPST_PB_RA]  68.74 2.72 270 top
SW3  EVQPUA02K  [SW_SPST_PB_4P8X3P5_SM]  96.15 103.42 180 top
SW5  ATCA Handle Switch  [SW2_SPST_PB_RA]  89.88 2.84 270 top
SW6  ATCA Handle Switch  [SW2_SPST_PB_RA]  96.78 2.82 270 top
SW7  EVQPUA02K  [SW_SPST_PB_4P8X3P5_SM]  104.32 103.42 180 top
SW8  ATCA Handle Switch  [SW2_SPST_PB_RA]  103.7 2.81 270 top
T1  RJ45-8  [HFJ11-2450E-L12RL]  46.93 14.4 90 top
TP3  TEST_POINT  [TESTPOINT_060_035MIL]  31.82 70.42 0 top
TP4  TEST_POINT  [TESTPOINT_060_035MIL]  5.64 1.9 0 top
TP5  TEST_POINT  [TESTPOINT_060_035MIL]  113.25 13.65 0 top
TP8  35 MIL  [TESTPOINT_35MIL]  21.75 62.41 0 top
TP11  TEST_POINT  [TESTPOINT_060_035MIL]  108.35 40.81 180 bottom
TP12  TEST_POINT  [TESTPOINT_060_035MIL]  106.01 28.37 180 bottom
TP13  35 MIL  [TESTPOINT_35MIL]  12.98 61.19 180 bottom
TP14  35 MIL  [TESTPOINT_35MIL]  13.88 60.62 180 bottom
TP15  35 MIL  [TESTPOINT_35MIL]  109.28 14.35 0 top
TP16  35 MIL  [TESTPOINT_35MIL]  107.04 17 0 top
TVS1  EGA10402V05A2  [0402_MLP]  16.54 19.34 180 top
TVS2  EGA10201V00A3  [0201_CC]  20.9 17.05 270 top
U1  MCIMX283DVM4B  [BGA289_0P8_14X14]  56.64 47.63 0 bottom
U2  MT47H64M16HR  [FBGA_84_0P8_10X12P5]  72.75 50.46 0 bottom
U3  LAN8720A  [QFN24_4X4MM_SLUG]  33.84 45.22 90 bottom
U4  MC12311  [LGA60_0P5_8X8]  19.91 63.87 90 bottom
U5  MT29F4G08ABADAWP  [TSOP48]  47.88 64.78 0 bottom
U14  1.8V  [SOT23-5_A]  15 52.65 180 bottom
U15  MC13226V  [LGA145_9P5_SQ]  104.29 48.74 180 bottom
U16  LM2735X  [LLP6_0P95_3X3]  86.71 53.64 0 bottom
U17  PCA9555BS  [QFN24_4X4_EP2P25MM]  66.88 66.99 270 bottom
U19  SGTL5000 32QFN  [QFN32]  102.56 34.94 270 bottom
U20  LM2735X  [LLP6_0P95_3X3]  95.46 10.41 180 bottom
U22  LT1938  [DFN10]  79.12 36.14 90 bottom
U25  USB2513  [QFN36]  30.55 32.7 90 bottom
U28  LM3671MF-3.3  [SOT23_5S]  18.27 40.91 90 bottom
U29  LM3671MF-3.3  [SOT23_5S]  34.25 65.06 180 top
U30  NC7SZ08P5  [SC70-5]  75.67 35.46 0 bottom
U31  NC7SZ08P5  [SC70-5]  24.25 29.37 0 bottom
U32  TPS2064  [MSOP8_0P65_3P1X3P1]  24.42 24.27 0 bottom
U33  TPS2064  [MSOP8_0P65_3P1X3P1]  83.96 10.72 90 bottom
U34  USB2SERA10CFK  [QFN24_0P65_5X5]  104.93 11.52 270 top
U35  USB_TYPE_A  [CON_4_USB]  75.92 12.94 90 top
U40  MC74HC32A  [TSSOP14_A]  14.96 31 90 bottom
U41  PICOREAD  [SSOP16]  76.28 77.64 0 bottom
U42  ZXCL330E5TA  [SOT23-5]  26.77 60.09 0 top
Y2  32.768KHZ  [XTAL2-3P2X1P5-SM]  51.98 36.26 270 bottom
Y3  24MHZ  [XTLOSC4_3P2X2P5MM_SM]  56.92 35.72 0 bottom
Y4  32MHZ  [XTLOSC4_3P2X2P5MM_SM]  26.38 63.77 270 bottom
Y5  24MHZ  [XTLOSC4_3P2X2P5MM_SM]  100.41 57.13 270 bottom
Y7  24MHZ  [XTLOSC4_3P2X2P5MM_SM]  37.59 33.79 270 bottom
Y8  12MHz  [XTLOSC4_3P2X2P5MM_SM]  110.62 10.94 90 top
Y9  13.56MHz  [XTAL_CS10_SM]  78.7 77.8 90 top

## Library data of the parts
ANT1 = F_Antenna
C1-C35 C51 C52 C57-C207 C209-C232 C238-C305 = CAP_NP
C208 C233-C237 = CAP_POL
D3 D35-D42 = LED_DUAL_SEP2_RG
D4 D6 D11 D12 D17 = DIODE_SCHTKY
D7 D8 = LED
D43 = BAT721B
D44 = BZX84C27
D45 = ZDIODE
E5 E6 = ANTENNA_2P4GHZ
F1 = FUSE_RESETTABLE
FL1-FL8 = EMIFILTER_NFA18SD
J5 = DC_POWER_JACK_3
J7 J8 = USB_MINI_AB_RECEPTACLE
J9 J10 J12 J14 = UFL
J11 = CONN_HDR_3X2
J13 = QSH060
J15-J17 = CONN_HDR_3X1
J18 = 3.5MM_STEREO_JACK
J20 = MINI_PCI_LATCH_52P
J22 = USB_A_DUAL
J23 = CONN_HDR_4X1
L1-L9 L11 L12 L15 L16 L18-L20 L27 L28 L30 = INDUCTOR
L10 = IND
L13 = BEAD
L21-L26 = INDUCTOR_FERRITE
L29 L31-L34 = 42H171000
P2 = CONN_PCB_2X5
Q4 Q9 Q16-Q20 = MOSFET_N
Q5 Q6 Q13 Q14 = MOSFET_P_6P
Q15 = TRIAC_2A
R1-R20 R25-R27 R39 R41-R47 R49 R51-R58 R64 R66 R68 R69 R75-R78 R80-R110 R118-R132 R134-R138 R140-R153 R155-R188 R193-R214 = RES
RN6 RN7 = RES_ISO8_SINGLE
RN8 RN9 = Resistor_Array
S1 = SW_DIP-2
SW2 SW5 SW6 SW8 = SW2_SPST_PB
SW3 SW7 = EDGE_MOUNT_PB_SW_2
T1 = HFJ11-2450E-L12RL
TP3-TP5 TP11 TP12 = T POINT TH
TP8 TP13-TP16 = Test pad: Tolerance: TOLERANCE; User Part Number: 510-75219
TVS1 TVS2 = DIODE_TVS_BIDIR
U1 = PCIMX287DJM4A_MAPBGA_289P
U2 = MT47H32M16BN-37E
U3 = LAN8720A-QFN24
U4 = MC12311_LGA_60P
U5 = K9F2G08U0A_48P
U14 = MC78PC18NTR_1
U15 = MC13224V_145P
U16 U20 = LM2735XSD
U17 = PCA9555BS
U19 = SGTL5000
U22 = LT1938_DFN10
U25 = USB2513_QFN_36P
U28 U29 = LM3671
U30 U31 = ONE_AND
U32 U33 = ST2042_1
U34 = USB2SERA10CFK
U35 = 292336-2
U40 = 4X_2IN_OR_14P_HETERO
U41 = PICOREAD
U42 = ZXCL330E5TA
Y2 = XTAL
Y3 Y5 Y7 Y8 = CRYSTAL_JXS63
Y4 = XTAL_13Y
Y9 = XTAL_CS10

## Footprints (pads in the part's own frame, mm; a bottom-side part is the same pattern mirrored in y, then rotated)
0201_CC
  rect 0.305x0.305 smd: 1(-0.267,0) 2(0.267,0)
0402_MLP
  rect 0.9x0.7 smd: 1(-0.65,0) 2(0.65,0)
AMP-787745-X
  rect 1.6x1.6 hole 0.94: A1(0,0)
  round 1.6 hole 0.94: A2(2.489,0) A3(4.496,0) A4(6.985,0) B1(0,-2.616) B2(2.489,-2.616) B3(4.496,-2.616) B4(6.985,-2.616)
  round 3.785 hole 2.286: S1(-3.073,0.356) S2(10.058,0.356) S3(-3.073,-5.334) S4(10.058,-5.334)
ANTENNA_3316
  rect 0.305x1.6 smd: 1(-1.5,0) 2(1.5,0)
BGA289_0P8_14X14
  round 0.305 smd: A1(-6.4,6.4) A2(-5.6,6.4) A3(-4.8,6.4) A4(-4,6.4) A5(-3.2,6.4) A6(-2.4,6.4) A7(-1.6,6.4) A8(-0.8,6.4) A9(0,6.4) A10(0.8,6.4) A11(1.6,6.4) A12(2.4,6.4) A13(3.2,6.4) A14(4,6.4) A15(4.8,6.4) A16(5.6,6.4) A17(6.4,6.4) B1(-6.4,5.6) B2(-5.6,5.6) B3(-4.8,5.6) B4(-4,5.6) B5(-3.2,5.6) B6(-2.4,5.6) B7(-1.6,5.6) B8(-0.8,5.6) B9(0,5.6) B10(0.8,5.6) B11(1.6,5.6) B12(2.4,5.6) B13(3.2,5.6) B14(4,5.6) B15(4.8,5.6) B16(5.6,5.6) B17(6.4,5.6) C1(-6.4,4.8) C2(-5.6,4.8) C3(-4.8,4.8) C4(-4,4.8) C5(-3.2,4.8) C6(-2.4,4.8) C7(-1.6,4.8) C8(-0.8,4.8) C9(0,4.8) C10(0.8,4.8) C11(1.6,4.8) C12(2.4,4.8) C13(3.2,4.8) C14(4,4.8) C15(4.8,4.8) C16(5.6,4.8) C17(6.4,4.8) D1(-6.4,4) D2(-5.6,4) D3(-4.8,4) D4(-4,4) D5(-3.2,4) D6(-2.4,4) D7(-1.6,4) D8(-0.8,4) D9(0,4) D10(0.8,4) D11(1.6,4) D12(2.4,4) D13(3.2,4) D14(4,4) D15(4.8,4) D16(5.6,4) D17(6.4,4) E1(-6.4,3.2) E2(-5.6,3.2) E3(-4.8,3.2) E4(-4,3.2) E5(-3.2,3.2) E6(-2.4,3.2) E7(-1.6,3.2) E8(-0.8,3.2) E9(0,3.2) E10(0.8,3.2) E11(1.6,3.2) E12(2.4,3.2) E13(3.2,3.2) E14(4,3.2) E15(4.8,3.2) E16(5.6,3.2) E17(6.4,3.2) F1(-6.4,2.4) F2(-5.6,2.4) F3(-4.8,2.4) F4(-4,2.4) F5(-3.2,2.4) F6(-2.4,2.4) F7(-1.6,2.4) F8(-0.8,2.4) F9(0,2.4) F10(0.8,2.4) F11(1.6,2.4) F12(2.4,2.4) F13(3.2,2.4) F14(4,2.4) F15(4.8,2.4) F16(5.6,2.4) F17(6.4,2.4) G1(-6.4,1.6) G2(-5.6,1.6) G3(-4.8,1.6) G4(-4,1.6) G5(-3.2,1.6) G6(-2.4,1.6) G7(-1.6,1.6) G8(-0.8,1.6) G9(0,1.6) G10(0.8,1.6) G11(1.6,1.6) G12(2.4,1.6) G13(3.2,1.6) G14(4,1.6) G15(4.8,1.6) G16(5.6,1.6) G17(6.4,1.6) H1(-6.4,0.8) H2(-5.6,0.8) H3(-4.8,0.8) H4(-4,0.8) H5(-3.2,0.8) H6(-2.4,0.8) H7(-1.6,0.8) H8(-0.8,0.8) H9(0,0.8) H10(0.8,0.8) H11(1.6,0.8) H12(2.4,0.8) H13(3.2,0.8) H14(4,0.8) H15(4.8,0.8) H16(5.6,0.8) H17(6.4,0.8) J1(-6.4,0) J2(-5.6,0) J3(-4.8,0) J4(-4,0) J5(-3.2,0) J6(-2.4,0) J7(-1.6,0) J8(-0.8,0) J9(0,0) J10(0.8,0) J11(1.6,0) J12(2.4,0) J13(3.2,0) J14(4,0) J15(4.8,0) J16(5.6,0) J17(6.4,0) K1(-6.4,-0.8) K2(-5.6,-0.8) K3(-4.8,-0.8) K4(-4,-0.8) K5(-3.2,-0.8) K6(-2.4,-0.8) K7(-1.6,-0.8) K8(-0.8,-0.8) K9(0,-0.8) K10(0.8,-0.8) K11(1.6,-0.8) K12(2.4,-0.8) K13(3.2,-0.8) K14(4,-0.8) K15(4.8,-0.8) K16(5.6,-0.8) K17(6.4,-0.8) L1(-6.4,-1.6) L2(-5.6,-1.6) L3(-4.8,-1.6) L4(-4,-1.6) L5(-3.2,-1.6) L6(-2.4,-1.6) L7(-1.6,-1.6) L8(-0.8,-1.6) L9(0,-1.6) L10(0.8,-1.6) L11(1.6,-1.6) L12(2.4,-1.6) L13(3.2,-1.6) L14(4,-1.6) L15(4.8,-1.6) L16(5.6,-1.6) L17(6.4,-1.6) M1(-6.4,-2.4) M2(-5.6,-2.4) M3(-4.8,-2.4) M4(-4,-2.4) M5(-3.2,-2.4) M6(-2.4,-2.4) M7(-1.6,-2.4) M8(-0.8,-2.4) M9(0,-2.4) M10(0.8,-2.4) M11(1.6,-2.4) M12(2.4,-2.4) M13(3.2,-2.4) M14(4,-2.4) M15(4.8,-2.4) M16(5.6,-2.4) M17(6.4,-2.4) N1(-6.4,-3.2) N2(-5.6,-3.2) N3(-4.8,-3.2) N4(-4,-3.2) N5(-3.2,-3.2) N6(-2.4,-3.2) N7(-1.6,-3.2) N8(-0.8,-3.2) N9(0,-3.2) N10(0.8,-3.2) N11(1.6,-3.2) N12(2.4,-3.2) N13(3.2,-3.2) N14(4,-3.2) N15(4.8,-3.2) N16(5.6,-3.2) N17(6.4,-3.2) P1(-6.4,-4) P2(-5.6,-4) P3(-4.8,-4) P4(-4,-4) P5(-3.2,-4) P6(-2.4,-4) P7(-1.6,-4) P8(-0.8,-4) P9(0,-4) P10(0.8,-4) P11(1.6,-4) P12(2.4,-4) P13(3.2,-4) P14(4,-4) P15(4.8,-4) P16(5.6,-4) P17(6.4,-4) R1(-6.4,-4.8) R2(-5.6,-4.8) R3(-4.8,-4.8) R4(-4,-4.8) R5(-3.2,-4.8) R6(-2.4,-4.8) R7(-1.6,-4.8) R8(-0.8,-4.8) R9(0,-4.8) R10(0.8,-4.8) R11(1.6,-4.8) R12(2.4,-4.8) R13(3.2,-4.8) R14(4,-4.8) R15(4.8,-4.8) R16(5.6,-4.8) R17(6.4,-4.8) T1(-6.4,-5.6) T2(-5.6,-5.6) T3(-4.8,-5.6) T4(-4,-5.6) T5(-3.2,-5.6) T6(-2.4,-5.6) T7(-1.6,-5.6) T8(-0.8,-5.6) T9(0,-5.6) T10(0.8,-5.6) T11(1.6,-5.6) T12(2.4,-5.6) T13(3.2,-5.6) T14(4,-5.6) T15(4.8,-5.6) T16(5.6,-5.6) T17(6.4,-5.6) U1(-6.4,-6.4) U2(-5.6,-6.4) U3(-4.8,-6.4) U4(-4,-6.4) U5(-3.2,-6.4) U6(-2.4,-6.4) U7(-1.6,-6.4) U8(-0.8,-6.4) U9(0,-6.4) U10(0.8,-6.4) U11(1.6,-6.4) U12(2.4,-6.4) U13(3.2,-6.4) U14(4,-6.4) U15(4.8,-6.4) U16(5.6,-6.4) U17(6.4,-6.4)
CASE_B
  rect 1.524x3.048 smd: 1(-1.27,0) 2(1.27,0)
CC0402_25
  round 0.635 smd: 1(-0.508,0) 2(0.508,0)
CC0603_OV
  oval 0.889x1.143 smd: 1(-0.762,0) 2(0.762,0)
CC0805_OV
  oval 0.889x1.524 smd: 1(-0.965,0) 2(0.965,0)
CC3216
  rect 2.032x1.397 smd: 1(-1.397,0) 2(1.397,0)
CC6032
  rect 3.175x2.54 smd: 1(-2.286,0) 2(2.286,0)
CON5_MICROUSB
  rect 1.803x1.905 smd: (-1.15,0) (1.15,0)
  rect 0.381x1.346 smd: 1(-1.3,2.675) 2(-0.65,2.675) 3(0,2.675) 4(0.65,2.675) 5(1.3,2.675)
  oval 1.067x1.397 hole 0.762x0.864: S1(-2.225,3) S2(2.225,3)
  rect 2.108x1.905 smd: S3(-3.65,0) S4(3.65,0)
CON_2X5_FTS_SM
  rect 0.737x2.997 smd: 1(-2.54,-1.803) 2(-2.54,1.803) 3(-1.27,-1.803) 4(-1.27,1.803) 5(0,-1.803) 6(0,1.803) 7(1.27,-1.803) 8(1.27,1.803) 9(2.54,-1.803) 10(2.54,1.803)
CON_2X26_0P8_SMT_A
  rect 2.311x3.2 smd: (-14.65,3.5) (14.65,3.5)
  round 0.254 hole 1.118 unplated: (-12.5,0)
  rect 5.791x5.791 hole 3.2: (-12.1,-23.9) (12.1,-23.9)
  round 0.254 hole 1.6 unplated: (12.5,0)
  rect 0.61x2.007 smd: 1(11.8,4.1) 2(11.4,-4.1) 3(11,4.1) 4(10.6,-4.1) 5(10.2,4.1) 6(9.8,-4.1) 7(9.4,4.1) 8(9,-4.1) 9(8.6,4.1) 10(8.2,-4.1) 11(7.8,4.1) 12(7.4,-4.1) 13(7,4.1) 14(6.6,-4.1) 15(6.2,4.1) 16(5.8,-4.1) 17(2.2,4.1) 18(1.8,-4.1) 19(1.4,4.1) 20(1,-4.1) 21(0.6,4.1) 22(0.2,-4.1) 23(-0.2,4.1) 24(-0.6,-4.1) 25(-1,4.1) 26(-1.4,-4.1) 27(-1.8,4.1) 28(-2.2,-4.1) 29(-2.6,4.1) 30(-3,-4.1) 31(-3.4,4.1) 32(-3.8,-4.1) 33(-4.2,4.1) 34(-4.6,-4.1) 35(-5,4.1) 36(-5.4,-4.1) 37(-5.8,4.1) 38(-6.2,-4.1) 39(-6.6,4.1) 40(-7,-4.1) 41(-7.4,4.1) 42(-7.8,-4.1) 43(-8.2,4.1) 44(-8.6,-4.1) 45(-9,4.1) 46(-9.4,-4.1) 47(-9.8,4.1) 48(-10.2,-4.1) 49(-10.6,4.1) 50(-11,-4.1) 51(-11.4,4.1) 52(-11.8,-4.1)
CON_3_UFL_R_SMT
  rect 1.016x1.067 smd: 1(0,1.524)
  rect 1.067x2.21 smd: 2(-1.476,0) 3(1.476,0)
CON_4_USB
  rect 1.6x1.6 hole 0.965: 1(0,0)
  round 1.6 hole 0.965: 2(2,0) 3(4,0) 4(6,0)
  round 2.261 hole 1.346: S1(-0.73,2.72) S2(-0.73,-2.72) S3(6.27,-2.72) S4(6.27,2.72)
CON_120S_QSH_SM_05PITCH
  round 0.254 hole 1.016 unplated: (-20.06,2.66) (20.07,2.66)
  rect 0.279x2.286 smd: 1(-17.25,-2.86) 2(-17.25,2.86) 3(-16.75,-2.86) 4(-16.75,2.86) 5(-16.25,-2.86) 6(-16.25,2.86) 7(-15.75,-2.86) 8(-15.75,2.86) 9(-15.25,-2.86) 10(-15.25,2.86) 11(-14.75,-2.86) 12(-14.75,2.86) 13(-14.25,-2.86) 14(-14.25,2.86) 15(-13.75,-2.86) 16(-13.75,2.86) 17(-13.25,-2.86) 18(-13.25,2.86) 19(-12.75,-2.86) 20(-12.75,2.86) 21(-12.25,-2.86) 22(-12.25,2.86) 23(-11.75,-2.86) 24(-11.75,2.86) 25(-11.25,-2.86) 26(-11.25,2.86) 27(-10.75,-2.86) 28(-10.75,2.86) 29(-10.25,-2.86) 30(-10.25,2.86) 31(-9.75,-2.86) 32(-9.75,2.86) 33(-9.25,-2.86) 34(-9.25,2.86) 35(-8.75,-2.86) 36(-8.75,2.86) 37(-8.25,-2.86) 38(-8.25,2.86) 39(-7.75,-2.86) 40(-7.75,2.86) 41(-7.25,-2.86) 42(-7.25,2.86) 43(-6.75,-2.86) 44(-6.75,2.86) 45(-6.25,-2.86) 46(-6.25,2.86) 47(-5.75,-2.86) 48(-5.75,2.86) 49(-5.25,-2.86) 50(-5.25,2.86) 51(-4.75,-2.86) 52(-4.75,2.86) 53(-4.25,-2.86) 54(-4.25,2.86) 55(-3.75,-2.86) 56(-3.75,2.86) 57(-3.25,-2.86) 58(-3.25,2.86) 59(-2.75,-2.86) 60(-2.75,2.86) 61(2.75,-2.86) 62(2.75,2.86) 63(3.25,-2.86) 64(3.25,2.86) 65(3.75,-2.86) 66(3.75,2.86) 67(4.25,-2.86) 68(4.25,2.86) 69(4.75,-2.86) 70(4.75,2.86) 71(5.25,-2.86) 72(5.25,2.86) 73(5.75,-2.86) 74(5.75,2.86) 75(6.25,-2.86) 76(6.25,2.86) 77(6.75,-2.86) 78(6.75,2.86) 79(7.25,-2.86) 80(7.25,2.86) 81(7.75,-2.86) 82(7.75,2.86) 83(8.25,-2.86) 84(8.25,2.86) 85(8.75,-2.86) 86(8.75,2.86) 87(9.25,-2.86) 88(9.25,2.86) 89(9.75,-2.86) 90(9.75,2.86) 91(10.25,-2.86) 92(10.25,2.86) 93(10.75,-2.86) 94(10.75,2.86) 95(11.25,-2.86) 96(11.25,2.86) 97(11.75,-2.86) 98(11.75,2.86) 99(12.25,-2.86) 100(12.25,2.86) 101(12.75,-2.86) 102(12.75,2.86) 103(13.25,-2.86) 104(13.25,2.86) 105(13.75,-2.86) 106(13.75,2.86) 107(14.25,-2.86) 108(14.25,2.86) 109(14.75,-2.86) 110(14.75,2.86) 111(15.25,-2.86) 112(15.25,2.86) 113(15.75,-2.86) 114(15.75,2.86) 115(16.25,-2.86) 116(16.25,2.86) 117(16.75,-2.86) 118(16.75,2.86) 119(17.25,-2.86) 120(17.25,2.86)
  rect 2.54x0.432 smd: SH1(-18.055,0) SH4(-1.935,0) SH5(1.935,0) SH8(18.055,0)
  rect 4.699x0.432 smd: SH2(-13.17,0) SH3(-6.82,0) SH6(6.82,0) SH7(13.17,0)
CON_AUD_3_TH_RA
  rect 1.626x2.642 hole 1.016x2.032: 1(0,0) 2(2.4,1.999) 3(7.899,1.999)
CONN_DC_POWER_3P
  oval 4.699x1.524 hole 4.191x1.016: 1(0,0) 3(0,-6.223)
  oval 1.524x4.699 hole 1.016x4.191: 2(4.953,-3.111)
CRN_8_0P5_2X1
  rect 0.508x0.406 smd: 1(-0.5,0.75) 4(-0.5,-0.75) 5(0.5,-0.75) 8(0.5,0.75)
  rect 0.508x0.305 smd: 2(-0.5,0.25) 3(-0.5,-0.25) 6(0.5,-0.25) 7(0.5,0.25)
DFN10
  rect 0.686x0.254 smd: 1(-1.413,1) 2(-1.413,0.5) 3(-1.413,0) 4(-1.413,-0.5) 5(-1.413,-1) 6(1.413,-1) 7(1.413,-0.5) 8(1.413,0) 9(1.413,0.5) 10(1.413,1)
  rect 1.651x2.388 smd: 11(0,0)
DIP-SMT2
  rect 3.175x1.778 smd: 1(-4.763,1.27) 2(-4.763,-1.27) 3(4.763,-1.27) 4(4.763,1.27)
F_ANTENNA_DIG528-2
  custom 0.212x0.212 smd: 1(0,0)
  round 0 hole 0.305: 2(5.933,-1.144)
FBGA_84_0P8_10X12P5
  round 0.381 smd: A1(-3.2,5.6) A2(-2.4,5.6) A3(-1.6,5.6) A7(1.6,5.6) A8(2.4,5.6) A9(3.2,5.6) B1(-3.2,4.8) B2(-2.4,4.8) B3(-1.6,4.8) B7(1.6,4.8) B8(2.4,4.8) B9(3.2,4.8) C1(-3.2,4) C2(-2.4,4) C3(-1.6,4) C7(1.6,4) C8(2.4,4) C9(3.2,4) D1(-3.2,3.2) D2(-2.4,3.2) D3(-1.6,3.2) D7(1.6,3.2) D8(2.4,3.2) D9(3.2,3.2) E1(-3.2,2.4) E2(-2.4,2.4) E3(-1.6,2.4) E7(1.6,2.4) E8(2.4,2.4) E9(3.2,2.4) F1(-3.2,1.6) F2(-2.4,1.6) F3(-1.6,1.6) F7(1.6,1.6) F8(2.4,1.6) F9(3.2,1.6) G1(-3.2,0.8) G2(-2.4,0.8) G3(-1.6,0.8) G7(1.6,0.8) G8(2.4,0.8) G9(3.2,0.8) H1(-3.2,0) H2(-2.4,0) H3(-1.6,0) H7(1.6,0) H8(2.4,0) H9(3.2,0) J1(-3.2,-0.8) J2(-2.4,-0.8) J3(-1.6,-0.8) J7(1.6,-0.8) J8(2.4,-0.8) J9(3.2,-0.8) K2(-2.4,-1.6) K3(-1.6,-1.6) K7(1.6,-1.6) K8(2.4,-1.6) K9(3.2,-1.6) L1(-3.2,-2.4) L2(-2.4,-2.4) L3(-1.6,-2.4) L7(1.6,-2.4) L8(2.4,-2.4) M2(-2.4,-3.2) M3(-1.6,-3.2) M7(1.6,-3.2) M8(2.4,-3.2) M9(3.2,-3.2) N1(-3.2,-4) N2(-2.4,-4) N3(-1.6,-4) N7(1.6,-4) N8(2.4,-4) P2(-2.4,-4.8) P3(-1.6,-4.8) P7(1.6,-4.8) P8(2.4,-4.8) P9(3.2,-4.8) R1(-3.2,-5.6) R2(-2.4,-5.6) R3(-1.6,-5.6) R7(1.6,-5.6) R8(2.4,-5.6)
FILTER_NFA18SD
  oval 0.178x0.457 smd: 1(0,0.879) 2(0,-0.879)
  oval 0.457x0.178 smd: 3(0.48,0.6) 4(0.48,0.2) 5(0.48,-0.2) 6(0.48,-0.6) 7(-0.48,0.6) 8(-0.48,0.2) 9(-0.48,-0.2) 10(-0.48,-0.6)
FUSE_SMDC150F
  rect 0.991x1.6 smd: 1(-1.5,0) 2(1.5,0)
HDR103_78MIL
  rect 1.499x1.499 hole 0.889: 1(0,0)
  round 1.499 hole 0.889: 2(-2,0) 3(-4,0)
HDR104_929
  rect 1.676x1.676 hole 1.016: 1(0,0)
  round 1.676 hole 1.016: 2(0,-2.54) 3(0,-5.08) 4(0,-7.62)
HDR203_TSM2_SM
  rect 3.175x1.27 smd: 1(-2.667,2.54) 2(2.667,2.54) 3(-2.667,0) 4(2.667,0) 5(-2.667,-2.54) 6(2.667,-2.54)
HFJ11-2450E-L12RL
  round 0.254 hole 3.251 unplated: (-6.35,1.27) (-6.35,-10.16)
  round 1.473 hole 0.889: 1(0,0) 2(2.54,-1.27) 3(0,-2.54) 4(2.54,-3.81) 5(0,-5.08) 6(2.54,-6.35) 7(0,-7.62) 8(2.54,-8.89)
  round 1.524 hole 1.016: 9(-10.41,2.185) 10(-10.41,-0.355) 11(-10.41,-8.535) 12(-10.41,-11.075)
  round 2.083 hole 1.575: 13(-3.302,3.302) 14(-3.302,-12.192)
IND_0402
  round 0.635 smd: 1(-0.508,0) 2(0.508,0)
IND_0603
  rect 0.991x0.813 smd: 1(-0.69,0) 2(0.69,0)
IND_0603A
  rect 1.016x1.016 smd: 1(-0.69,0) 2(0.69,0)
IND_0805_4P
  rect 0.813x0.508 smd: 1(0.835,0.435) 2(-0.835,0.435) 3(-0.835,-0.435) 4(0.835,-0.435)
IND_IHLP_2020
  rect 1.93x2.794 smd: 1(-2.032,0) 2(2.032,0)
IND_VLF4018
  rect 1.575x3.886 smd: 1(-1.448,0) 2(1.448,0)
IND_VLF5014A
  rect 0.914x1.6 smd: 1(-2.4,0) 2(2.4,0)
IND_VLS3012_SM
  rect 1.016x3.023 smd: 1(-1,0) 2(1,0)
LED_0603
  rect 1.016x1.016 smd: A(-0.762,0) C(0.762,0)
LED_DUAL_0605_SM
  rect 0.85x0.65 smd: 1(-0.725,0.425) 2(-0.725,-0.425) 3(0.725,0.425) 4(0.725,-0.425)
LGA60_0P5_8X8
  oval 0.711x0.254 smd: 1(-3.878,3.25) 2(-3.878,2.75) 3(-3.878,2.25) 4(-3.878,1.75) 5(-3.878,1.25) 6(-3.878,0.75) 7(-3.878,0.25) 8(-3.878,-0.25) 9(-3.878,-0.75) 10(-3.878,-1.25) 11(-3.878,-1.75) 12(-3.878,-2.25) 13(-3.878,-2.75) 14(-3.878,-3.25) 29(3.878,-3.25) 30(3.878,-2.75) 31(3.878,-2.25) 32(3.878,-1.75) 33(3.878,-1.25) 34(3.878,-0.75) 35(3.878,-0.25) 36(3.878,0.25) 37(3.878,0.75) 38(3.878,1.25) 39(3.878,1.75) 40(3.878,2.25) 41(3.878,2.75) 42(3.878,3.25)
  oval 0.254x0.711 smd: 15(-3.25,-3.878) 16(-2.75,-3.878) 17(-2.25,-3.878) 18(-1.75,-3.878) 19(-1.25,-3.878) 20(-0.75,-3.878) 21(-0.25,-3.878) 22(0.25,-3.878) 23(0.75,-3.878) 24(1.25,-3.878) 25(1.75,-3.878) 26(2.25,-3.878) 27(2.75,-3.878) 28(3.25,-3.878) 43(3.25,3.878) 44(2.75,3.878) 45(2.25,3.878) 46(1.75,3.878) 47(1.25,3.878) 48(0.75,3.878) 49(0.25,3.878) 50(-0.25,3.878) 51(-0.75,3.878) 52(-1.25,3.878) 53(-1.75,3.878) 54(-2.25,3.878) 55(-2.75,3.878) 56(-3.25,3.878)
  rect 0.356x0.356 smd: 57(1.75,-1.75) 58(2.75,-1.75) 59(1.75,-2.75) 60(2.75,-2.75)
  rect 2.769x2.896 smd: 61(-1.5,-1.4)
  rect 2.616x2.616 smd: 62(1.5,1.5)
LGA145_9P5_SQ
  custom 0.075x0.075 smd: 1(-4.6,3.75) 2(-4.6,3.25) 3(-4.6,2.75) 4(-4.6,2.25) 5(-4.6,1.75) 6(-4.6,1.249) 7(-4.6,0.749) 8(-4.6,0.249) 9(-4.6,-0.251) 10(-4.6,-0.751) 11(-4.6,-1.251) 12(-4.6,-1.751) 13(-4.6,-2.252) 14(-4.6,-2.752) 15(-4.6,-3.252) 16(-4.6,-3.752) 17(-3.75,-4.6) 18(-3.25,-4.6) 19(-2.75,-4.6) 20(-2.25,-4.6) 21(-1.75,-4.6) 22(-1.249,-4.6) 23(-0.749,-4.6) 24(-0.249,-4.6) 25(0.251,-4.6) 26(0.751,-4.6) 27(1.251,-4.6) 28(1.751,-4.6) 29(2.252,-4.6) 30(2.752,-4.6) 31(3.252,-4.6) 32(3.752,-4.6) 33(4.6,-3.75) 34(4.6,-3.25) 35(4.6,-2.75) 36(4.6,-2.25) 37(4.6,-1.75) 38(4.6,-1.249) 39(4.6,-0.749) 40(4.6,-0.249) 41(4.6,0.251) 42(4.6,0.751) 43(4.6,1.251) 44(4.6,1.751) 45(4.6,2.252) 46(4.6,2.752) 47(4.6,3.252) 48(4.6,3.752) 49(3.75,4.6) 50(3.25,4.6) 51(2.75,4.6) 52(2.25,4.6) 53(1.75,4.6) 54(1.249,4.6) 55(0.749,4.6) 56(0.249,4.6) 57(-0.251,4.6) 58(-0.751,4.6) 59(-1.251,4.6) 60(-1.751,4.6) 61(-2.252,4.6) 62(-2.752,4.6) 63(-3.252,4.6) 64(-3.752,4.6)
  rect 0.508x0.508 smd: 65(-3.2,3.2) 66(-2.4,3.2) 67(-1.6,3.2) 68(-0.8,3.2) 69(0,3.2) 70(0.8,3.2) 71(1.6,3.2) 72(2.4,3.2) 73(3.2,3.2) 74(-3.2,2.4) 75(-2.4,2.4) 76(-1.6,2.4) 77(-0.8,2.4) 78(0,2.4) 79(0.8,2.4) 80(1.6,2.4) 81(2.4,2.4) 82(3.2,2.4) 83(-3.2,1.6) 84(-2.4,1.6) 85(-1.6,1.6) 86(-0.8,1.6) 87(0,1.6) 88(0.8,1.6) 89(1.6,1.6) 90(2.4,1.6) 91(3.2,1.6) 92(-3.2,0.8) 93(-2.4,0.8) 94(-1.6,0.8) 95(-0.8,0.8) 96(0,0.8) 97(0.8,0.8) 98(1.6,0.8) 99(2.4,0.8) 100(3.2,0.8) 101(-3.2,0) 102(-2.4,0) 103(-1.6,0) 104(-0.8,0) 105(0,0) 106(0.8,0) 107(1.6,0) 108(2.4,0) 109(3.2,0) 110(-3.2,-0.8) 111(-2.4,-0.8) 112(-1.6,-0.8) 113(-0.8,-0.8) 114(0,-0.8) 115(0.8,-0.8) 116(1.6,-0.8) 117(2.4,-0.8) 118(3.2,-0.8) 119(-3.2,-1.6) 120(-2.4,-1.6) 121(-1.6,-1.6) 122(-0.8,-1.6) 123(0,-1.6) 124(0.8,-1.6) 125(1.6,-1.6) 126(2.4,-1.6) 127(3.2,-1.6) 128(-3.2,-2.4) 129(-2.4,-2.4) 130(-1.6,-2.4) 131(-0.8,-2.4) 132(0,-2.4) 133(0.8,-2.4) 134(1.6,-2.4) 135(2.4,-2.4) 136(3.2,-2.4) 137(-3.2,-3.2) 138(-2.4,-3.2) 139(-1.6,-3.2) 140(-0.8,-3.2) 141(0,-3.2) 142(0.8,-3.2) 143(1.6,-3.2) 144(2.4,-3.2) 145(3.2,-3.2)
LLP6_0P95_3X3
  rect 0.66x0.356 smd: 1(-1.4,0.95) 2(-1.4,0) 3(-1.4,-0.95) 4(1.4,-0.95) 5(1.4,0) 6(1.4,0.95)
  rect 1.6x2.108 smd: 7(0,0)
MSOP8_0P65_3P1X3P1
  rect 0.889x0.432 smd: 1(-2.23,0.975) 2(-2.23,0.325) 3(-2.23,-0.325) 4(-2.23,-0.975) 5(2.23,-0.975) 6(2.23,-0.325) 7(2.23,0.325) 8(2.23,0.975)
  rect 1.727x2.362 smd: 9(0,0)
QFN24_0P65_5X5
  oval 0.813x0.356 smd: 1(-2.44,1.625) 2(-2.44,0.975) 3(-2.44,0.325) 4(-2.44,-0.325) 5(-2.44,-0.975) 6(-2.44,-1.625) 13(2.44,-1.625) 14(2.44,-0.975) 15(2.44,-0.325) 16(2.44,0.325) 17(2.44,0.975) 18(2.44,1.625)
  oval 0.356x0.813 smd: 7(-1.625,-2.44) 8(-0.975,-2.44) 9(-0.325,-2.44) 10(0.325,-2.44) 11(0.975,-2.44) 12(1.625,-2.44) 19(1.625,2.44) 20(0.975,2.44) 21(0.325,2.44) 22(-0.325,2.44) 23(-0.975,2.44) 24(-1.625,2.44)
  rect 3.708x3.708 smd: 25(0,0)
QFN24_4X4_EP2P25MM
  oval 0.279x0.813 smd: 1(-1.25,-1.956) 2(-0.75,-1.956) 3(-0.25,-1.956) 4(0.25,-1.956) 5(0.75,-1.956) 6(1.25,-1.956) 13(1.25,1.956) 14(0.75,1.956) 15(0.25,1.956) 16(-0.25,1.956) 17(-0.75,1.956) 18(-1.25,1.956)
  oval 0.813x0.279 smd: 7(1.956,-1.25) 8(1.956,-0.75) 9(1.956,-0.25) 10(1.956,0.25) 11(1.956,0.75) 12(1.956,1.25) 19(-1.956,1.25) 20(-1.956,0.75) 21(-1.956,0.25) 22(-1.956,-0.25) 23(-1.956,-0.75) 24(-1.956,-1.25)
  rect 2.235x2.235 smd: 25(0,0)
QFN24_4X4MM_SLUG
  oval 0.279x0.711 smd: 1(-1.25,-1.956) 2(-0.75,-1.956) 3(-0.25,-1.956) 4(0.25,-1.956) 5(0.75,-1.956) 6(1.25,-1.956) 13(1.25,1.956) 14(0.75,1.956) 15(0.25,1.956) 16(-0.25,1.956) 17(-0.75,1.956) 18(-1.25,1.956)
  oval 0.711x0.279 smd: 7(1.956,-1.25) 8(1.956,-0.75) 9(1.956,-0.25) 10(1.956,0.25) 11(1.956,0.75) 12(1.956,1.25) 19(-1.956,1.25) 20(-1.956,0.75) 21(-1.956,0.25) 22(-1.956,-0.25) 23(-1.956,-0.75) 24(-1.956,-1.25)
  rect 2.616x2.616 smd: 25(0,0)
QFN32
  custom 0.07x0.07 smd: 1(-2.4,1.751) 2(-2.4,1.251) 3(-2.4,0.751) 4(-2.4,0.25) 5(-2.4,-0.25) 6(-2.4,-0.751) 7(-2.4,-1.251) 8(-2.4,-1.751) 9(-1.751,-2.4) 10(-1.251,-2.4) 11(-0.751,-2.4) 12(-0.25,-2.4) 13(0.25,-2.4) 14(0.751,-2.4) 15(1.251,-2.4) 16(1.751,-2.4) 17(2.4,-1.751) 18(2.4,-1.251) 19(2.4,-0.751) 20(2.4,-0.25) 21(2.4,0.25) 22(2.4,0.751) 23(2.4,1.251) 24(2.4,1.751) 25(1.751,2.4) 26(1.251,2.4) 27(0.751,2.4) 28(0.25,2.4) 29(-0.25,2.4) 30(-0.751,2.4) 31(-1.251,2.4) 32(-1.751,2.4)
  rect 3.454x3.454 smd: 33(0,0)
QFN36
  oval 1.016x0.279 smd: 1(-2.764,2.002) 2(-2.764,1.501) 3(-2.764,1.001) 4(-2.764,0.5) 5(-2.764,0) 6(-2.764,-0.498) 7(-2.764,-0.998) 8(-2.764,-1.499) 9(-2.764,-1.999) 19(2.774,-1.999) 20(2.774,-1.499) 21(2.774,-0.998) 22(2.774,-0.498) 23(2.774,0) 24(2.774,0.5) 25(2.774,1.001) 26(2.774,1.501) 27(2.774,2.002)
  oval 0.279x1.016 smd: 10(-1.999,-2.774) 11(-1.499,-2.774) 12(-0.998,-2.774) 13(-0.498,-2.774) 14(0,-2.774) 15(0.5,-2.774) 16(1.001,-2.774) 17(1.501,-2.774) 18(2.002,-2.774) 28(2.002,2.774) 29(1.501,2.774) 30(1.001,2.774) 31(0.5,2.774) 32(0,2.774) 33(-0.498,2.774) 34(-0.998,2.774) 35(-1.499,2.774) 36(-1.999,2.774)
  rect 3.861x3.861 smd: 37(0,0)
